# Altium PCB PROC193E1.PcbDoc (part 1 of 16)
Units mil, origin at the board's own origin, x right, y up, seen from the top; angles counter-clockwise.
Board outline 7700 x 2300 mil, 6 copper layers (Top Layer, GND 1, SIG 1, PWR, GND 2, Bottom Layer), stack 60.98 mil thick; 946 components, 667 nets, 9401 pads, 1730 vias.
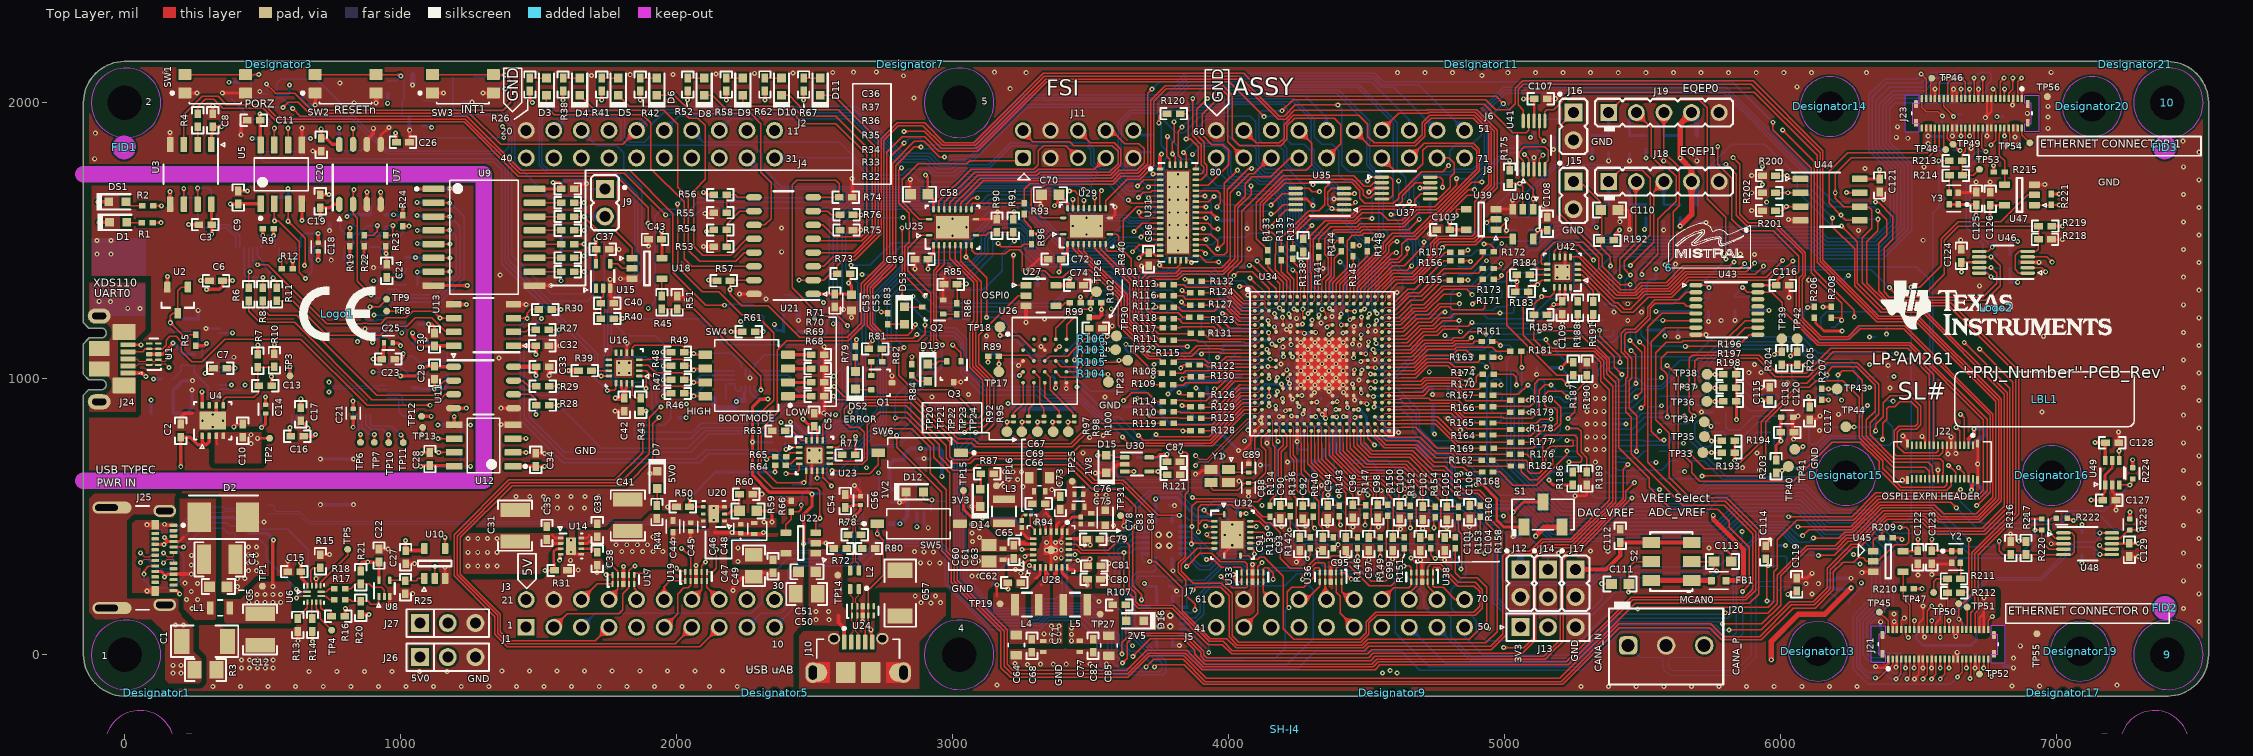
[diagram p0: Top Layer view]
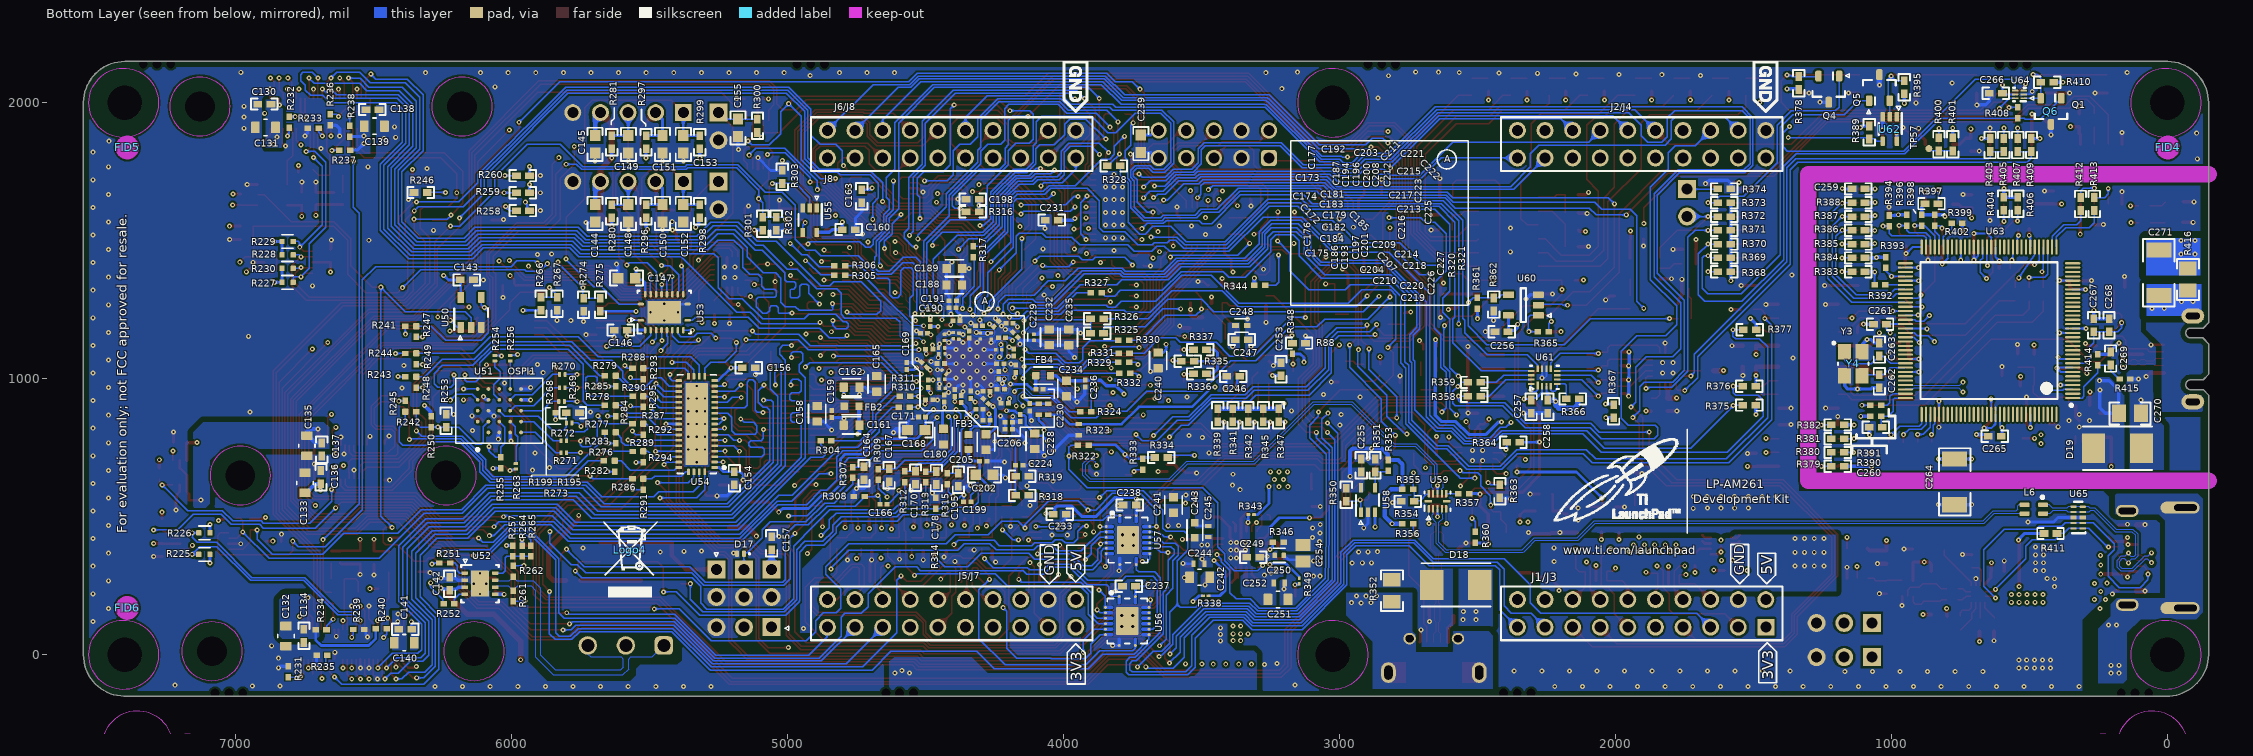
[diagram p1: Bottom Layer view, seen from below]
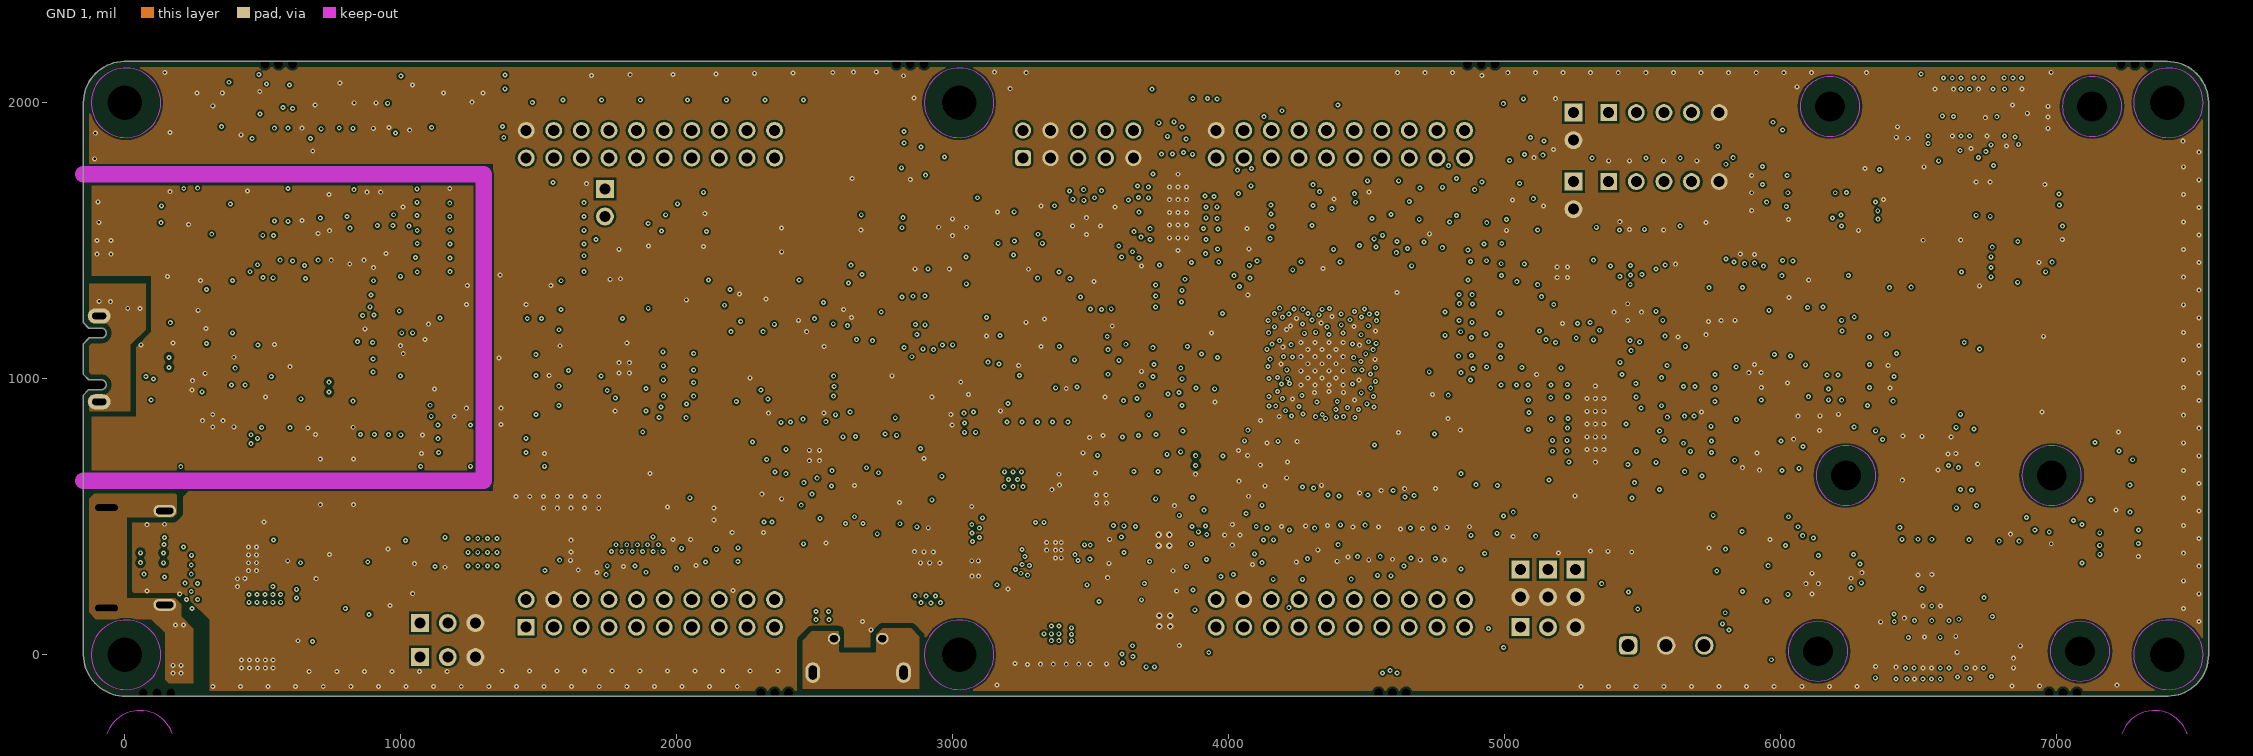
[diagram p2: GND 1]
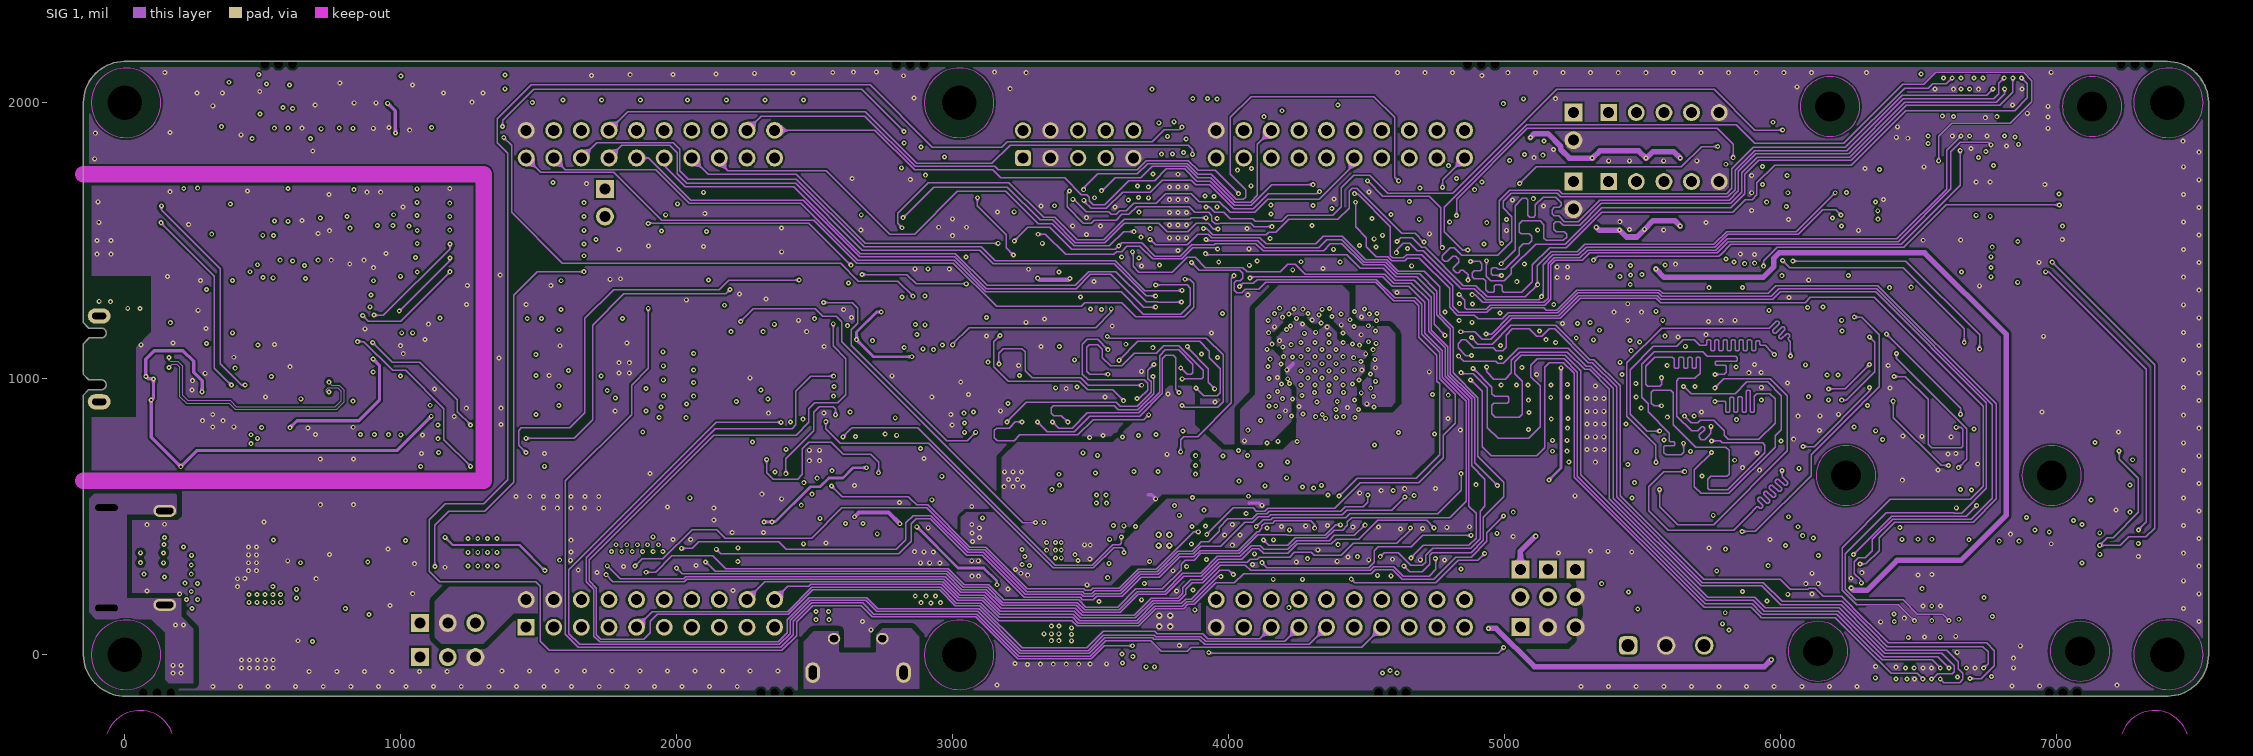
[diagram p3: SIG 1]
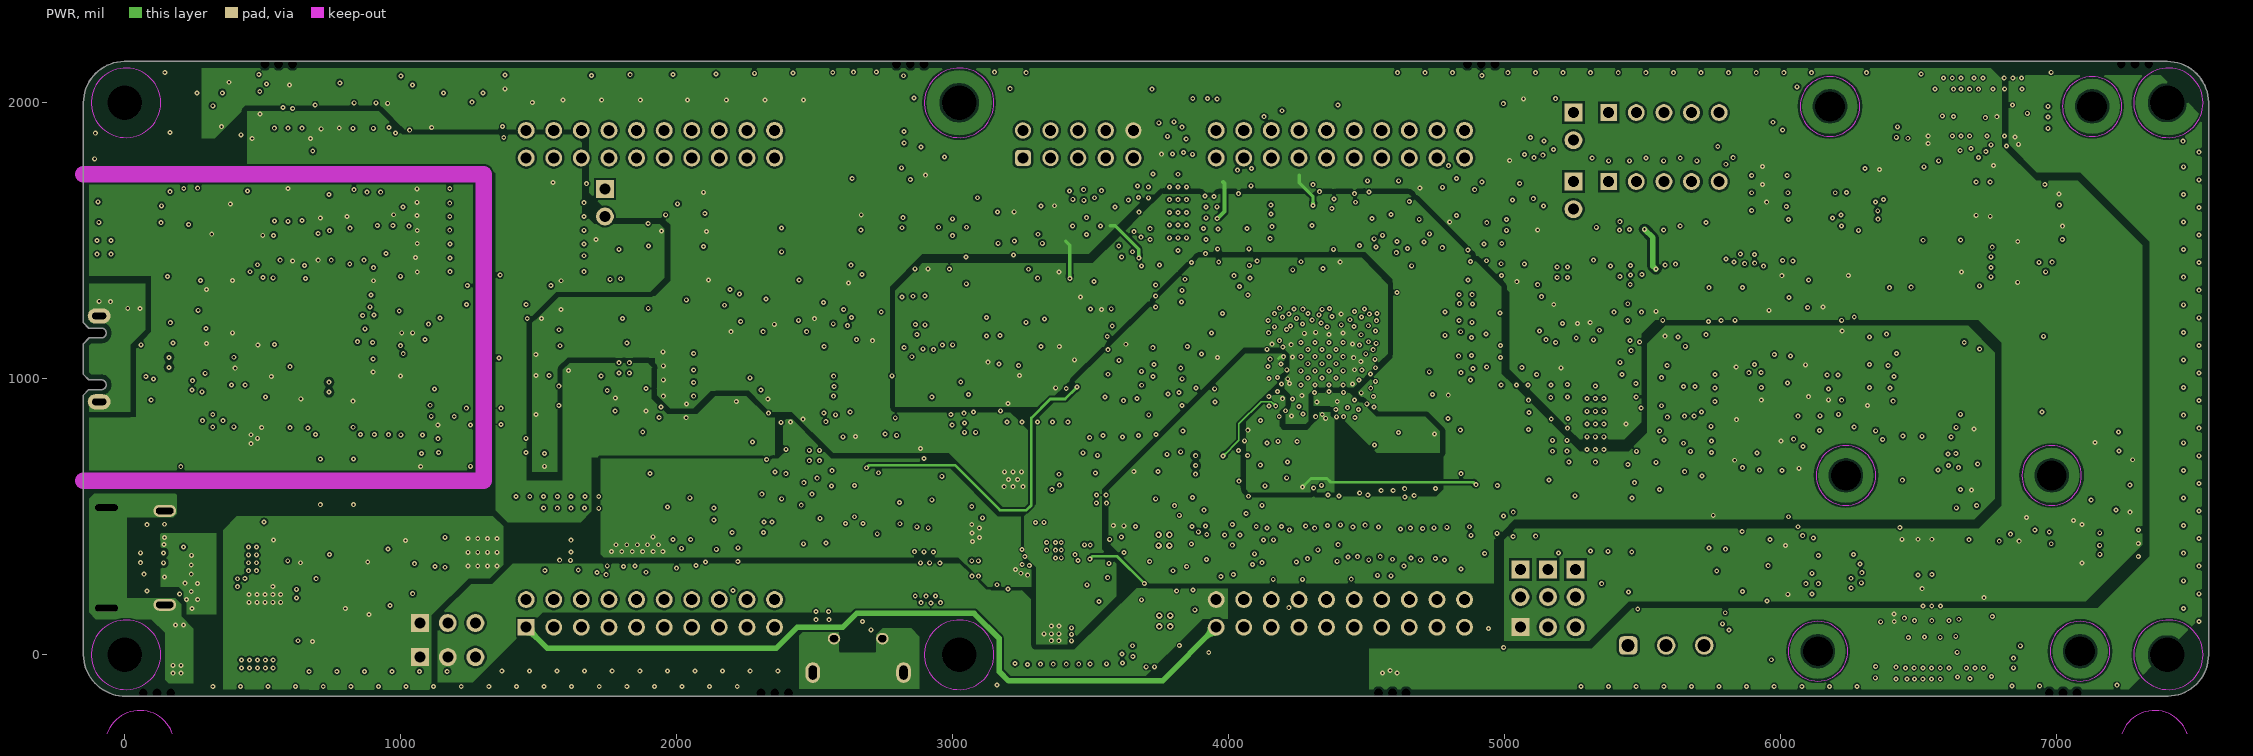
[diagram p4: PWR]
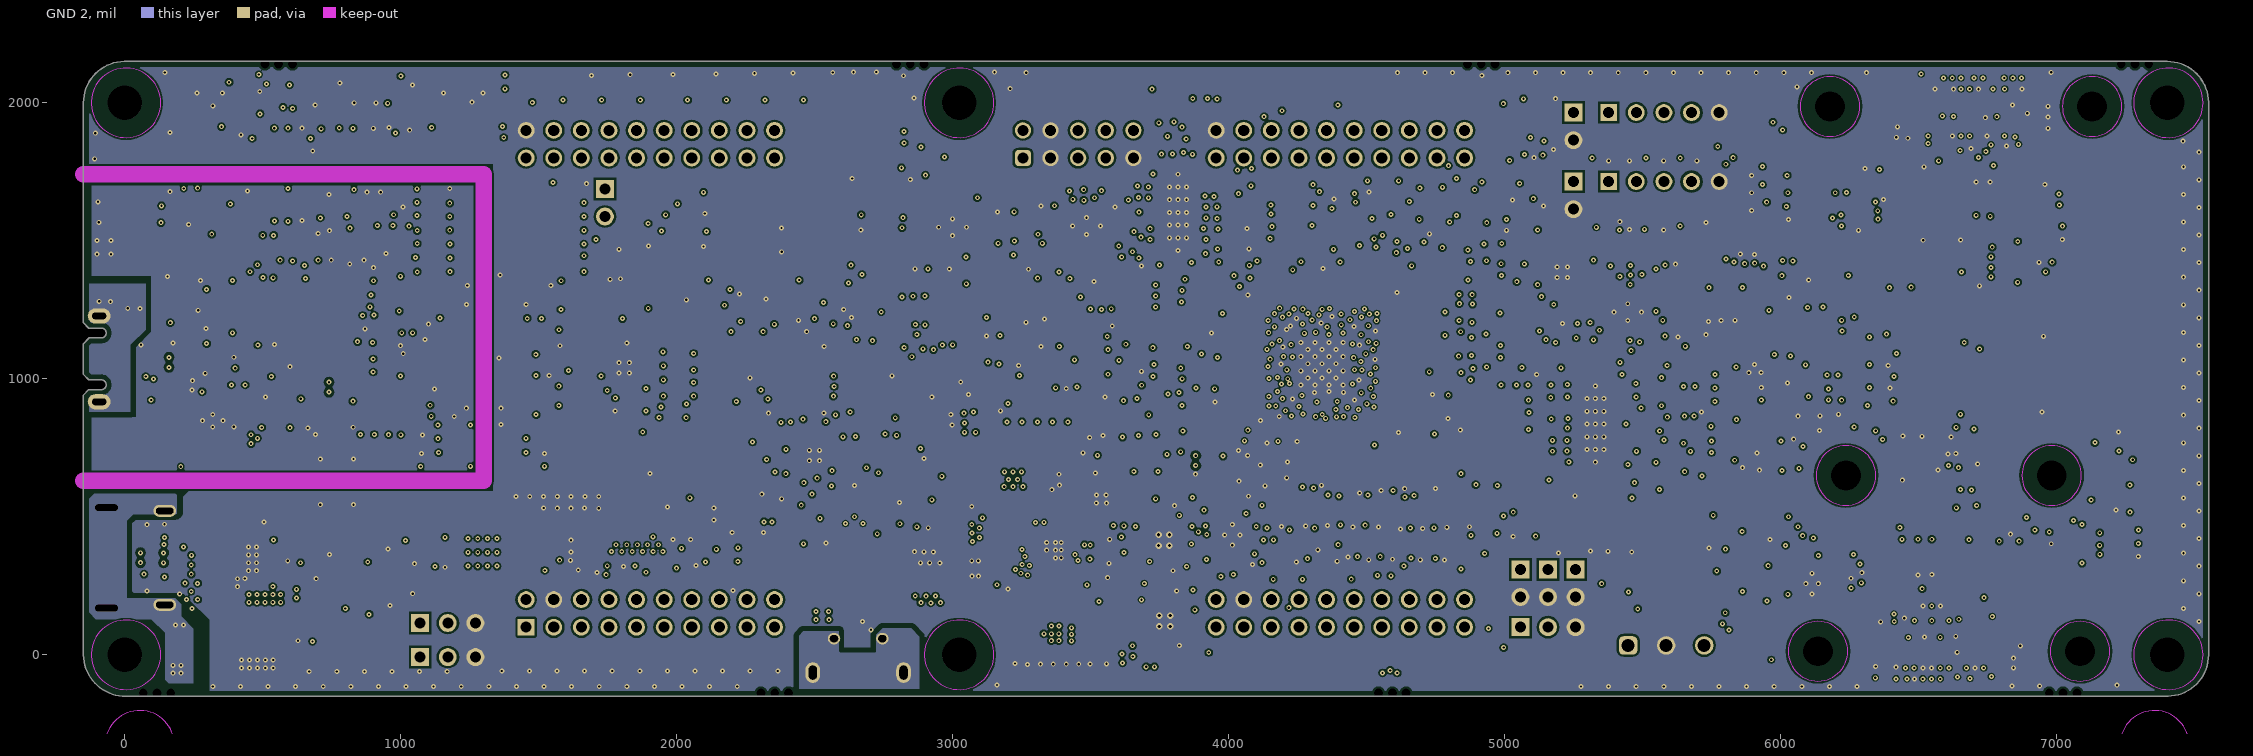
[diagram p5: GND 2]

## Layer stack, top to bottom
Top Solder: solder mask 1, ELECTRA EMP 110/5410- RED, Dk 4
Top Layer: signal copper 1.85
Dielectric 1: prepreg 3.55, Iteq IT180A Prepreg 2113 RC58, Dk 4.13
GND 1: signal copper 1.26
Dielectric 3: core 4, Iteq IT180A 4 mil core 1/1, Dk 4.4
SIG 1: signal copper 1.26
Dielectric 5: core 1.859, Iteq IT180A Prepreg 106 RC71.5, Dk 3.79
Dielectric 7: core 2.711, Iteq IT180A Prepreg 1080 RC65, Dk 3.86
Dielectric1: core 28, Iteq IT180A 28 mil core H/H, Dk 4.53
Dielectric 8: core 2.711, Iteq IT180A Prepreg 1080 RC65, Dk 3.86
Dielectric 6: core 1.859, Iteq IT180A Prepreg 106 RC71.5, Dk 3.79
PWR: signal copper 1.26
Dielectric 4: core 4, Iteq IT180A 4 mil core 1/1, Dk 4.4
GND 2: signal copper 1.26
Dielectric 2: prepreg 3.55, Iteq IT180A Prepreg 2113 RC58, Dk 4.13
Bottom Layer: signal copper 1.85
Bottom Solder: solder mask 1, ELECTRA EMP 110/5410- RED, Dk 4

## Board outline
-150,0 -150,941.28 -130.32,960.97 -84.25,960.97 ccw(c-84.25,977.87) -67.34,977.87 ccw(c-85.87,977.87) -85.87,996.4 -130.32,996.4 -150,1016.08 -150,1127.3 -130.32,1146.99 -130.32,1147.97 -85.04,1147.97 ccw(c-85.04,1165.67) -67.34,1165.67 -67.34,1166.5 ccw(c-84.25,1166.5) -84.25,1183.41 -130.32,1183.41 -150,1203.09 -150,1278.88 -150,1999.99 cw(c0,2000) -2.06,2149.99 0,2150 7399.99,2150 cw(c7400,2000) 7549.99,2002.06 7550,2000 7550,0.01 cw(c7400,0) 7402.06,-149.99 7400,-149.99 0,-150 4.17,-150 cw(c2.09,2.09)

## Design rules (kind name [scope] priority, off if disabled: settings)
AssemblyTestPointUsage [All] p1: valid=2
BoardOutlineClearance BoardOutlineClearance_MountingHoles [OnCopper and InComponentClass('Mounting Holes')] p1: gap=39.37 ignorepadtopadclearanceinfootprint=FALSE
BoardOutlineClearance "Outline Exception" [HasFootprint('Molex_1051640001') or HasFootprint('BRAKE_WAY_HOLES1X3') or HasFootprint('MHNP_M3_PANHEAD_PHILLIPS') or HasFootprint('Fiducial10-20')] p2: gap=0 ignorepadtopadclearanceinfootprint=FALSE
BoardOutlineClearance BoardOutlineClearance_Poly [OnCopper and IsPoly] p3: gap=25 ignorepadtopadclearanceinfootprint=FALSE except(20: Poly-OutlineEdge)
BoardOutlineClearance [OnCopper and Not InComponentClass('Logo') and not InComponentClass('FiducialMark') and not InRegion(1000,500,4000,800) and not InPoly] p4: gap=40 ignorepadtopadclearanceinfootprint=FALSE except(15: SMDPad-OutlineEdge THPad-OutlineEdge; 20: Poly-OutlineEdge; 25: Arc-OutlineEdge Track-OutlineEdge Via-OutlineEdge Fill-OutlineEdge Text-OutlineEdge)
Clearance RGMII_2W_INT [InNetClass('RGMII') and (OnLayer('SIG 1')) vs not InNetClass('RGMII')] p1: gap=7.87 ignorepadtopadclearanceinfootprint=TRUE except(6: SMDPad-SMDPad Via-Fill Via-Poly Via-Region; 7: Via-Via; 7.4: Arc-SMDPad Track-SMDPad; 7.5: SMDPad-Via; 9.5: Arc-Arc Arc-Track Track-Track; 10: Poly-Region; 20: Region-Region; 25: Fill-Fill Fill-Poly Fill-Region Poly-Poly)
Clearance RGMII_INT [InNetClass('RGMII') vs OnLayer('SIG 1')] p2: gap=7.87 ignorepadtopadclearanceinfootprint=TRUE except(6: SMDPad-SMDPad Via-Fill Via-Poly Via-Region; 7: Via-Via; 7.12: Arc-Arc Arc-Track Track-Track; 7.4: Arc-SMDPad Track-SMDPad; 7.5: SMDPad-Via; 10: Poly-Region; 20: Region-Region; 25: Fill-Fill Fill-Poly Fill-Region Poly-Poly)
Clearance RGMII_2W_EXT [InNetClass('RGMII') and OnBottomLayer vs not InNetClass('RGMII')] p3: gap=7.87 ignorepadtopadclearanceinfootprint=TRUE except(6: SMDPad-SMDPad Via-Fill Via-Poly Via-Region; 7: Via-Via; 7.4: Arc-SMDPad Track-SMDPad; 7.5: SMDPad-Via; 10: Poly-Region; 10.6: Arc-Arc Arc-Track Track-Track; 20: Region-Region; 25: Fill-Fill Fill-Poly Fill-Region Poly-Poly)
Clearance RGMII_EXT [InNetClass('RGMII') vs OnLayer('Bottom Layer')] p4: gap=7.87 ignorepadtopadclearanceinfootprint=TRUE except(6: SMDPad-SMDPad Via-Fill Via-Poly Via-Region; 7: Via-Via; 7.12: Arc-Arc Arc-Track Track-Track; 7.4: Arc-SMDPad Track-SMDPad; 7.5: SMDPad-Via; 10: Poly-Region; 20: Region-Region; 25: Fill-Fill Fill-Poly Fill-Region Poly-Poly)
Clearance SOC_POLY_4MIL [WithinRoom('SOC_POLY')] p5: gap=4 ignorepadtopadclearanceinfootprint=TRUE except(3.94: Track-SMDPad; 15: Poly-Poly)
Clearance "Ethernet Conn" [(WithinRoom('Ethernet Conn1') or WithinRoom('Ethernet Conn2')or WithinRoom('12-Pin UQFN') or WithinRoom('Dual Schmitt-Trigger Buffer')or WithinRoom('PMIC') or WithinRoom('Mltplxr/Demltplxr1') or WithinRoom('Mltplxr/Demltplxr2'))] p6: gap=4 ignorepadtopadclearanceinfootprint=TRUE except(8: Region-Region; 12: Poly-Poly)
Clearance 90E_CLR_same [InDifferentialPairClass('90E')] p7: gap=7.87 ignorepadtopadclearanceinfootprint=TRUE except(5: Arc-Arc Arc-Track Track-Track; 10: Via-Fill Via-Poly Via-Region Poly-Region; 12: Via-Via; 20: Region-Region; 25: Fill-Fill Fill-Poly Fill-Region Poly-Poly)
Clearance 90E_CLR [InDifferentialPairClass('90E')] p8: gap=7.87 ignorepadtopadclearanceinfootprint=TRUE except(6: Via-Fill Via-Poly Via-Region; 10: Arc-Arc Arc-Track Track-Track Poly-Region; 12: Via-Via; 20: Region-Region; 25: Fill-Fill Fill-Poly Fill-Region Poly-Poly)
Clearance ADC_EXT [(OnLayer('Top Layer') or OnLayer('Bottom Layer')) vs InNetClass('ADC0')] p9: gap=7.87 ignorepadtopadclearanceinfootprint=TRUE except(5.3: Arc-Arc Arc-Track Track-Track; 6: Via-Fill Via-Poly Via-Region; 10: Poly-Region; 12: Via-Via; 20: Region-Region; 25: Fill-Fill Fill-Poly Fill-Region Poly-Poly)
Clearance ADC_SIG1 [OnLayer('SIG 1') vs InNetClass('ADC0')] p10: gap=7.87 ignorepadtopadclearanceinfootprint=TRUE except(4.75: Arc-Arc Arc-Track Track-Track; 6: Via-Fill Via-Poly Via-Region; 10: Poly-Region; 12: Via-Via; 20: Region-Region; 25: Fill-Fill Fill-Poly Fill-Region Poly-Poly)
Clearance 120E_CLR_same [InDifferentialPairClass('120E')] p11: gap=7.87 ignorepadtopadclearanceinfootprint=TRUE except(6.8: Arc-Arc Arc-Track Track-Track; 10: Via-Fill Via-Poly Via-Region Poly-Region; 12: Via-Via; 20: Region-Region; 25: Fill-Fill Fill-Poly Fill-Region Poly-Poly)
Clearance 120E_CLR [InDifferentialPairClass('120E')] p12: gap=7.87 ignorepadtopadclearanceinfootprint=TRUE except(6: Via-Fill Via-Poly Via-Region; 10: Poly-Region; 12: Via-Via; 15: Arc-Arc Arc-Track Track-Track; 20: Region-Region; 25: Fill-Fill Fill-Poly Fill-Region Poly-Poly)
Clearance DIff_spacing [All vs InDifferentialPair('XDSET_1_D')] p13: gap=7.87 ignorepadtopadclearanceinfootprint=TRUE except(5: Arc-Arc Arc-Track Track-Track; 6: Via-Fill Via-Poly Via-Region; 10: Poly-Region; 12: Via-Via; 20: Region-Region; 25: Fill-Fill Fill-Poly Fill-Region Poly-Poly)
Clearance PMIC_Clearance [InNetClass('PMIC') vs InPolygon] p14: gap=10 ignorepadtopadclearanceinfootprint=TRUE except(4: Via-Fill Via-Poly Via-Region; 12: Fill-Fill Fill-Poly Fill-Region Poly-Poly Poly-Region Region-Region)
Clearance Clearance_FIDUCIAL [HasFootprint('Fiducial10-20')] p15: gap=7.87 ignorepadtopadclearanceinfootprint=TRUE except(0: Arc-SMDPad; 5: Arc-Arc Arc-Track Track-Track; 6: Via-Fill Via-Poly Via-Region; 7: Track-Via; 10: Poly-Region; 12: Via-Via; 20: Poly-Poly Region-Region; 25: Fill-Fill Fill-Poly Fill-Region)
Clearance "Clearance_J4 CONNECTOR" [HasFootprint('FP-DF40GB-48DP-0.4V(58)_HDR48-MFG')] p16: gap=7.87 ignorepadtopadclearanceinfootprint=TRUE except(0: SMDPad-Region; 5: Arc-Arc Arc-Track Track-Track; 6: Via-Fill Via-Poly Via-Region; 7: Track-Via; 10: Poly-Region; 12: Via-Via; 20: Poly-Poly Region-Region; 25: Fill-Fill Fill-Poly Fill-Region)
Clearance [All] p17: gap=7.87 ignorepadtopadclearanceinfootprint=TRUE except(5: Arc-Arc Arc-Track Track-Track; 6: Via-Fill Via-Poly Via-Region; 7: Track-Via; 10: Poly-Region; 12: Via-Via; 20: Poly-Poly Region-Region; 25: Fill-Fill Fill-Poly Fill-Region)
Clearance Clearance_Keepouts [IsKeepOut] p18: gap=1 ignorepadtopadclearanceinfootprint=FALSE
ComponentClearance ComponentClearance_EXCEPTION [HasFootprint('0402_070*')or HasFootprint('0402*')] p1: gap=8 collisioncheckmode=3 verticalgap=8 showdistances=FALSE
ComponentClearance ComponentClearance_MountingHoles_FiducialMarks [InComponentClass('Mounting Holes') vs InComponentClass('FiducialMark')] p2: gap=50 collisioncheckmode=3 verticalgap=10 showdistances=FALSE
ComponentClearance ComponentClearance_Shunt [InComponentClass('Header') vs InComponentClass('Shunt')] p3: gap=0 collisioncheckmode=3 verticalgap=0 showdistances=FALSE
ComponentClearance ComponentClearance_Logo [InComponentClass('Logo')] p4: gap=30 collisioncheckmode=3 verticalgap=10 showdistances=FALSE
ComponentClearance ComponentClearance_ScrewToNut [(HasFootprint('NY PMS 440 0025 PH')) vs (HasFootprint('Keystone_1902C'))] p5: gap=5 collisioncheckmode=3 verticalgap=10 showdistances=FALSE
ComponentClearance ComponentClearance_MountingHoles [InComponentClass('Mounting Holes')] p6: gap=100 collisioncheckmode=3 verticalgap=100000 showdistances=FALSE
ComponentClearance ComponentClearance_SmallPassives [HasFootprint('0201*') or HasFootprint('0508') or HasFootprint('0603*') or HasFootprint('0612') or HasFootprint('0805*') or HasFootprint('0815*') or HasFootprint('0830*') or HasFootprint('1206*') or HasFootprint('1210*') or HasFootprint('1808*') or HasFootprint('1812*') or HasFootprint('1825*') or HasFootprint('2010*') or HasFootprint('2220*') or HasFootprint('2225*') or HasFootprint('2512*') or HasFootprint('2728*') or HasFootprint('3518*') vs HasFootprint('0201*') or HasFootprint('0402*') or HasFootprint('0508') or HasFootprint('0603*') or HasFootprint('0612') or HasFootprint('0805*') or HasFootprint('0815*') or HasFootprint('0830*') or HasFootprint('1206*') or HasFootprint('1210*') or HasFootprint('1808*') or HasFootprint('1812*') or HasFootprint('1825*') or HasFootprint('2010*') or HasFootprint('2220*') or HasFootprint('2225*') or HasFootprint('2512*') or HasFootprint('2728*') or HasFootprint('3518*')] p7: gap=10 collisioncheckmode=3 verticalgap=10 showdistances=FALSE
ComponentClearance ComponentClearance_THtoSMT [IsThruComponent vs IsSMTComponent] p8: gap=30 collisioncheckmode=3 verticalgap=30 showdistances=FALSE
ComponentClearance ComponentClearance_THtoTH [IsThruComponent vs IsThruComponent] p9: gap=20 collisioncheckmode=3 verticalgap=30 showdistances=FALSE
ComponentClearance [All] p10: gap=15 collisioncheckmode=3 verticalgap=15 showdistances=TRUE
DiffPairsRouting 90E [InDifferentialPairClass('90E')] p1: maxlimit=10 minlimit=5 mostfreqgap=6 toplayer_prefgap=5 toplayer_minwidth=4.2 toplayer_maxwidth=15 toplayer_prefwidth=4.2 midlayer1_mingap=6 midlayer1_maxgap=6 midlayer1_minwidth=4 midlayer1_maxwidth=4 midlayer1_prefwidth=4 midlayer2_mingap=6 midlayer2_maxgap=6 midlayer2_minwidth=4 midlayer2_maxwidth=4 midlayer2_prefwidth=4 midlayer3_mingap=10 midlayer3_prefgap=10 midlayer3_minwidth=15 midlayer3_maxwidth=15 midlayer3_prefwidth=15 midlayer4_mingap=10 midlayer4_prefgap=10 midlayer4_minwidth=15 midlayer4_maxwidth=15 midlayer4_prefwidth=15 bottomlayer_prefgap=5 bottomlayer_minwidth=4.2 bottomlayer_maxwidth=15 bottomlayer_prefwidth=4.2 maxuncoupledlength=500
DiffPairsRouting 120E [InDifferentialPair('CANA')] p2: maxlimit=15 minlimit=10 mostfreqgap=10 toplayer_mingap=15 toplayer_prefgap=15 toplayer_minwidth=3.8 toplayer_maxwidth=15 toplayer_prefwidth=3.8 midlayer1_maxgap=10 midlayer1_minwidth=15 midlayer1_maxwidth=15 midlayer1_prefwidth=15 midlayer2_maxgap=10 midlayer2_minwidth=15 midlayer2_maxwidth=15 midlayer2_prefwidth=15 midlayer3_maxgap=10 midlayer3_minwidth=15 midlayer3_maxwidth=15 midlayer3_prefwidth=15 midlayer4_maxgap=10 midlayer4_minwidth=15 midlayer4_maxwidth=15 midlayer4_prefwidth=15 bottomlayer_mingap=15 bottomlayer_prefgap=15 bottomlayer_minwidth=3.8 bottomlayer_maxwidth=15 bottomlayer_prefwidth=3.8 maxuncoupledlength=500
DiffPairsRouting 100E_DIFF [InDifferentialPairClass('100E')] p3: maxlimit=100 minlimit=7.7 mostfreqgap=8.1 toplayer_maxgap=7.7 toplayer_prefgap=7.7 toplayer_minwidth=4 toplayer_maxwidth=4 toplayer_prefwidth=4 midlayer1_mingap=8.1 midlayer1_maxgap=8.1 midlayer1_minwidth=3.5 midlayer1_maxwidth=3.5 midlayer1_prefwidth=3.5 midlayer2_mingap=8.1 midlayer2_maxgap=8.1 midlayer2_minwidth=3.5 midlayer2_maxwidth=3.5 midlayer2_prefwidth=3.5 midlayer3_mingap=10 midlayer3_prefgap=10 midlayer3_minwidth=15 midlayer3_maxwidth=15 midlayer3_prefwidth=15 midlayer4_mingap=10 midlayer4_prefgap=10 midlayer4_minwidth=15 midlayer4_maxwidth=15 midlayer4_prefwidth=15 bottomlayer_maxgap=7.7 bottomlayer_prefgap=7.7 bottomlayer_minwidth=4 bottomlayer_maxwidth=4 bottomlayer_prefwidth=4 maxuncoupledlength=1000
FabricationTestPointUsage TestPointUsage [All] p1: valid=2 allowmultiple=FALSE
FabricationTestpoint Testpoint [All] p1: side=3 testpointundercomponent=TRUE minsize=40 maxsize=100 preferedsize=60 minholesize=0 maxholesize=40 preferedholesize=32 testpointgrid=1 allowsidetop=TRUE allowsidebottom=TRUE usegrid=TRUE gridtolerance=0.01
FanoutControl Fanout_LCC [IsLCC] p1: bgadir=Out bgaviamode=Centered fanoutstyle=Auto fanoutdirection=Alternating viagrid=1 // Fanout_LCC (Default Rule)
FanoutControl Fanout_BGA [IsBGA] p2: bgadir=Out bgaviamode=Centered fanoutstyle=Auto fanoutdirection=Alternating viagrid=1 // Fanout_BGA (Default Rule)
FanoutControl Fanout_Default [All] p4: bgadir=Out bgaviamode=Centered fanoutstyle=Auto fanoutdirection=Alternating viagrid=1 // Fanout_Default (Default Rule)
FanoutControl Fanout_Small [(CompPinCount < 5)] p5: bgadir=Out bgaviamode=Centered fanoutstyle=Auto fanoutdirection=OutThenIn viagrid=1 // Fanout_Small (Default Rule)
HoleSize [All] p1: absolutevalues=TRUE maxlimit=251 minlimit=7.87 maxpercent=80.000 minpercent=20.000
MatchedLengths XDSET [(InDifferentialPair('XDSET_1_D') or InDifferentialPair('AM261_USB2.0') or InDifferentialPair('CANA') or InDifferentialPair('USBMICROAB') or InDifferentialPair('USBMICROAB_C') or InDifferentialPair('USBTYPEC') or InDifferentialPair('USBTYPEC_C'))] p1: tolerance=1 checknetsindiffpair=TRUE checkdiffpairvsdiffpair=FALSE checkxsignals=FALSE checkothers=FALSE
MatchedLengths USB_TYPEC [InNetClass('USB_TYPEC')] p2: tolerance=10 checknetsindiffpair=TRUE checkdiffpairvsdiffpair=FALSE checkxsignals=FALSE checkothers=FALSE
MatchedLengths OPSI1_U34_U54 [InxSignalClass('OSPI1_U34_U54')] p3: tolerance=50 checknetsindiffpair=FALSE checkdiffpairvsdiffpair=TRUE checkxsignals=TRUE checkothers=TRUE targetsourcename=NetR218_2-AM261_OSPI1_CLK/FSITX0_CLK_PP1
MatchedLengths OSPI1_U54_J22 [InxSignalClass('OSPI1_U54_J22')] p4: tolerance=50 checknetsindiffpair=FALSE checkdiffpairvsdiffpair=TRUE checkxsignals=TRUE checkothers=TRUE targetsourcename=M_OSPI1_CLK-EX_OSPI1_CLK_PP2
MatchedLengths OSPI1_U54_51 [InxSignalClass('OSPI1_U54_U51')] p5: tolerance=50 checknetsindiffpair=FALSE checkdiffpairvsdiffpair=TRUE checkxsignals=TRUE checkothers=TRUE targetsourcename=M_OSPI1_CLK-OSPI1_CLK_PP1
MatchedLengths OSPI0_U34_U26 [InxSignalClass('OSPI0_U34_U26')] p6: tolerance=50 checknetsindiffpair=FALSE checkdiffpairvsdiffpair=TRUE checkxsignals=TRUE checkothers=TRUE targetsourcename=AM261_OSPI0_CLK
MatchedLengths RGMII1_TX [InxSignalClass('RGMII1_TX')] p7: tolerance=15 checknetsindiffpair=FALSE checkdiffpairvsdiffpair=TRUE checkxsignals=TRUE checkothers=TRUE targetsourcename=AM261_RGMII1_TD0_R-AM261_RGMII1_TD0_PP1
MatchedLengths RGMII1_RX [InxSignalClass('RGMII1_RX')] p8: tolerance=15 checknetsindiffpair=FALSE checkdiffpairvsdiffpair=TRUE checkxsignals=TRUE checkothers=TRUE targetsourcename=AM261_RGMII1_RD0_PP1
MatchedLengths RGMII2_TX [InxSignalClass('RGMII2_TX')] p9: tolerance=15 checknetsindiffpair=FALSE checkdiffpairvsdiffpair=TRUE checkxsignals=TRUE checkothers=TRUE targetsourcename=AM261_RGMII2_TD3-AM261_RGMII2_TD3_R_PP1
MatchedLengths RGMII2_RX [InxSignalClass('RGMII2_RX')] p10: tolerance=15 checknetsindiffpair=FALSE checkdiffpairvsdiffpair=TRUE checkxsignals=TRUE checkothers=TRUE targetsourcename=AM261_RGMII2_RD2_PP1
MinimumAnnularRing MinimumAnnularRing_ThermalPadVias [IsVia and InAnyComponent] p1: minimumring=5.91
MinimumAnnularRing [All] p2: minimumring=5
MinimumSolderMaskSliver MinimumSolderMaskSliver_Logo [InComponentClass('Logo') vs InComponentClass('Logo')] p1: minsoldermaskwidth=0.7
PlaneConnect [All] p1: planeconnectstyle=Direct reliefexpansion=10 reliefentries=4 reliefconductorwidth=10 reliefairgap=10
PolygonConnect PolygonConnect_3 [All vs IsNamedPolygon('SIG 2-vusb_3v3')] p1: connectstyle=Direct reliefconductorwidth=10 reliefentries=4 polygonreliefangle="90 Angle" airgapwidth=10
PolygonConnect PolygonConnect_2 [All vs IsNamedPolygon('Top Layer-VBUS_TYPEC_5V0')] p2: connectstyle=Direct reliefconductorwidth=10 reliefentries=4 polygonreliefangle="90 Angle" airgapwidth=10
PolygonConnect PolygonConnect_1 [All vs IsNamedPolygon('Top Layer-VBUS_TYPEC_5V0')] p3: connectstyle=Direct reliefconductorwidth=10 reliefentries=4 polygonreliefangle="90 Angle" airgapwidth=10
PolygonConnect [All] p4: connectstyle=Direct reliefconductorwidth=10 reliefentries=4 polygonreliefangle="90 Angle" airgapwidth=10
RoomDefinition Mltplxr/Demltplxr2 [InComponentClass('Room Definition8') vs False] p1: confinementstyle=ConfineIn formatcopy=TRUE lockcomponents=FALSE outline 3668.27,12.92 3668.27,264.38 3867.56,264.38 3867.56,12.92
RoomDefinition Mltplxr/Demltplxr1 [InComponentClass('Room Definition7') vs False] p2: confinementstyle=ConfineIn formatcopy=TRUE lockcomponents=FALSE outline 3665.4,306.14 3665.4,557.59 3864.69,557.59 3864.69,306.14
RoomDefinition PMIC [InComponentClass('Room Definition6') vs False] p3: confinementstyle=ConfineIn formatcopy=TRUE lockcomponents=FALSE outline 3240.34,274.86 3240.34,510.97 3459.53,510.97 3459.53,274.86
RoomDefinition "Dual Schmitt-Trigger Buffer" [InComponentClass('Room Definition5') vs False] p4: confinementstyle=ConfineIn formatcopy=TRUE lockcomponents=FALSE outline 491.1,1986.65 491.1,2073.74 579.76,2073.74 579.76,1986.65
RoomDefinition "12-Pin UQFN" [InComponentClass('Room Definition4') vs False] p5: confinementstyle=ConfineIn formatcopy=TRUE lockcomponents=FALSE outline 2577.63,461.21 2577.63,637.57 2710,637.57 2710,461.21
RoomDefinition "Ethernet Conn2" [InComponentClass('Room Definition3') vs False] p6: confinementstyle=ConfineIn formatcopy=TRUE lockcomponents=FALSE outline 6303.2,-125 6303.2,205.39 6819.03,205.39 6819.03,-125
RoomDefinition "Ethernet Conn1" [InComponentClass('Room Definition2') vs False] p7: confinementstyle=ConfineIn formatcopy=TRUE lockcomponents=FALSE outline 6434.39,1826 6434.39,2126 6950.22,2126 6950.22,1826
RoomDefinition SOC_POLY [False] p8: confinementstyle=ConfineIn formatcopy=TRUE lockcomponents=FALSE outline 4043.66,767.84 4043.66,1348.43 4624.25,1348.43 4624.25,767.84
RoutingLayers [All] p1: top layer_v5=TRUE mid layer 1_v5=TRUE mid layer 2_v5=TRUE mid layer 3_v5=FALSE mid layer 4_v5=TRUE bottom layer_v5=TRUE
RoutingVias ThermalPadVias [IsVia and InAnyComponent] p1: holewidth=7.87 width=19.68 viastyle="Through Hole" minholewidth=7.87 minwidth=19.68 maxholewidth=12.99 maxwidth=23.62
RoutingVias [All] p2: holewidth=8 width=18 viastyle="Through Hole" minholewidth=8 minwidth=18 maxholewidth=8 maxwidth=18
SilkToBoardRegionClearance [Not ((IsComment or IsDesignator) And (Hide <> 'False')) and not InRegion(1000,500,4000,800)] p1:
SilkToSilkClearance SilkToSilkClearance_Pb-FreeLogo [(HasFootprint('Pb-Free_Overlay_Medium') OR HasFootprint('Pb-Free_Overlay_Small')) vs (HasFootprint('Pb-Free_Overlay_Medium') OR HasFootprint('Pb-Free_Overlay_Small'))] p1: silktosilkclearance=0
SilkToSilkClearance [All] p2: silktosilkclearance=2
SilkToSolderMaskClearance SilkToComponentPadClearance [(IsPad or IsFill or IsRegion) and Component] p1: minsilkscreentomaskgap=3.54 clearancetoexposedcopper=TRUE
SilkToSolderMaskClearance "Silk to Solder Mask Opening" [All] p2: minsilkscreentomaskgap=1 clearancetoexposedcopper=FALSE
SolderMaskExpansion [All] p1: expansion=1.97 istentingtop=FALSE
UnRoutedNet [All] p1: checkbadconnections=TRUE
Width BGA-trace [All] p1: maxlimit=100 minlimit=3.94 preferedwidth=4.75 toplayer_prefwidth=3.94 midlayer1_minwidth=4.75 midlayer2_minwidth=4.75 midlayer3_minwidth=5.3 midlayer3_prefwidth=5.3 midlayer4_minwidth=5.3 midlayer4_prefwidth=5.3 bottomlayer_prefwidth=3.94 minimp=50.000000 maximp=50.000000 favimp=50.000000 checkconnectedcopper=TRUE
Width PWR [InNetClass('POWER')] p2: maxlimit=30 minlimit=6 preferedwidth=12 midlayer1_minwidth=8 midlayer2_minwidth=8 midlayer3_minwidth=8 midlayer4_minwidth=8 bottomlayer_minwidth=7 minimp=50.000000 maximp=50.000000 favimp=50.000000
Width [All] p3: maxlimit=100 minlimit=4.75 preferedwidth=5.3 toplayer_minwidth=5.3 midlayer1_prefwidth=4.75 midlayer2_prefwidth=4.75 midlayer3_minwidth=5.3 midlayer4_minwidth=5.3 bottomlayer_minwidth=5.3 minimp=50.000000 maximp=50.000000 favimp=50.000000 checkconnectedcopper=TRUE
13 further rules are at their usual default settings.

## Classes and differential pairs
net class USB_TYPEC: USBTYPEC_C_DM USBTYPEC_C_DP
net class 4MIL_SOC: AM261_ADC0_AIN0_R AM261_ADC0_AIN2_R AM261_ADC0_AIN5_R AM261_ADC1_AIN0_R AM261_ADC1_AIN3_R AM261_ADC1_AIN5_R AM261_ADC1_AIN6_R AM261_ADC2_AIN0_R AM261_ADC2_AIN3_R AM261_ADC2_AIN4_R AM261_CLKOUT1_R AM261_DAC_OUT_R AM261_EPWM2_B_R AM261_EPWM3_B_R AM261_EPWM4_A_R AM261_EPWM5_A_R AM261_EPWM6_A_R AM261_EPWM7_A_R AM261_EPWM7_B_R AM261_GPIO1 AM261_GPIO136 AM261_I2C0_SDA AM261_I2C1_SCL AM261_LIN2_RXD AM261_MCAN0_RX AM261_MCAN1_RX AM261_MCAN1_TX AM261_MII2_COL AM261_OSPI1_DQS/EQEP1_STROBE AM261_PORZ AM261_RGMII1_RD1 AM261_RGMII1_RX_CTL AM261_RGMII1_RXC AM261_RGMII1_TD3_R AM261_RGMII2_RD1 AM261_RGMII2_TD1_R AM261_RGMII2_TD3_R AM261_RGMII2_TXC_R AM261_RMII1_CRS_DV/MII1_CRS AM261_RMII2_RX_ER/MII2_RX_ER AM261_SPI0_CS0 AM261_SPI2_D1 AM261_UART3_TXD_R AM261_USB0_DRVVBUS NetR108_2 NetR109_2 NetR125_2 NetR126_2 NetR128_2 NetR129_2 NetR137_2 NetR138_2 NetR144_2 NetR145_2 NetR166_2 NetR167_2 NetR176_2 NetR177_2 NetR178_2 NetR182_2 NetR331_2 PR1_PRU0_GPIO0 PR1_PRU0_GPIO2 PR1_PRU0_GPIO5 PR1_PRU0_GPIO8 PR1_PRU1_GPIO0 PR1_PRU1_GPIO2 PR1_PRU1_GPIO13
net class FSI_U9-U46: M_FSITX0_CLK M_FSITX0_DATA0 M_FSITX0_DATA1
net class FSI_U9-U41: M_FSIRX0_CLK M_FSIRX0_DATA0/EQEP0_A M_FSIRX0_DATA1/EQEP0_B
net class FSI_U41-U46: FSIRX0_CLK FSIRX0_DATA0 FSIRX0_DATA1
net class FSI_U46-J23: FSIRX0_C FSIRX0_D0 FSIRX0_D1 FSITX0_C FSITX0_D0 FSITX0_D1
net class OSPI: AM261_OSPI0_CLK AM261_OSPI0_CSN0 AM261_OSPI0_D0 AM261_OSPI0_D1 AM261_OSPI0_D2 AM261_OSPI0_D3 AM261_OSPI0_D4 AM261_OSPI0_D5 AM261_OSPI0_D6 AM261_OSPI0_D7 AM261_OSPI0_DQS AM261_OSPI0_DQS_R AM261_OSPI0_ECC_FAIL AM261_OSPI0_RESET_OUT0 AM261_OSPI1_CLK/FSITX0_CLK AM261_OSPI1_CSN0/EQEP1_B AM261_OSPI1_D0/FSITX0_DATA0 AM261_OSPI1_D1/FSITX0_DATA1 AM261_OSPI1_D2/FSIRX0_CLK AM261_OSPI1_D3/FSIRX0_DATA0/EQEP0_A AM261_OSPI1_D4/FSIRX0_DATA1/EQEP0_B AM261_OSPI1_D5/EQEP0_INDEX AM261_OSPI1_D6/EQEP0_STROBE AM261_OSPI1_D7/EQEP1_A AM261_OSPI1_DQS/EQEP1_STROBE AM261_OSPI1_ECC_FAIL/EQEP1_INDEX AM261_OSPI1_RESET_OUT0 EX_OSPI1_CLK EX_OSPI1_CSN0 EX_OSPI1_CSN1 EX_OSPI1_D0 EX_OSPI1_D1 EX_OSPI1_D2 EX_OSPI1_D3 EX_OSPI1_D4 EX_OSPI1_D5 EX_OSPI1_D6 EX_OSPI1_D7 EX_OSPI1_DQS_R EX_OSPI1_ECC_FAIL EX_OSPI1_RSTn M_OSPI1_CLK M_OSPI1_CSN0 M_OSPI1_D0 M_OSPI1_D1 M_OSPI1_D2 M_OSPI1_D3 M_OSPI1_D4 M_OSPI1_D5 M_OSPI1_D6 M_OSPI1_D7 M_OSPI1_DQS M_OSPI1_ECC_FAIL OSPI0_D0 OSPI0_D1 OSPI0_D2 OSPI0_D3 OSPI0_D4 OSPI0_D5 OSPI0_D6 OSPI0_D7 OSPI0_RESET_OUT0 OSPI0_RSTn OSPI1_CLK OSPI1_CSN0 OSPI1_D0 OSPI1_D0_R OSPI1_D1 OSPI1_D1_R OSPI1_D2 OSPI1_D2_R OSPI1_D3 OSPI1_D3_R OSPI1_D4 OSPI1_D4_R OSPI1_D5 OSPI1_D5_R OSPI1_D6 OSPI1_D6_R OSPI1_D7 OSPI1_D7_R OSPI1_DQS OSPI1_DQS_R OSPI1_ECC_FAIL OSPI1_MUX_EN OSPI1_MUX_SEL OSPI1_RESET_OUT0 OSPI1_RSTn OSPI1_RSTn_R
net class 120E: CANA_N CANA_P
component class PROC193E1_19_USB_XDS110: C2 C10 C13 C14 C270 C271 D19 J24 R7 R10 R416 TP2 TP3 TP12 TP13 U1 U4
net class RGMII: AM261_RGMII1_RD0 AM261_RGMII1_RD1 AM261_RGMII1_RD2 AM261_RGMII1_RD3 AM261_RGMII1_RX_CTL AM261_RGMII1_RXC AM261_RGMII1_TD0 AM261_RGMII1_TD1 AM261_RGMII1_TD2 AM261_RGMII1_TD3 AM261_RGMII1_TX_CTL AM261_RGMII1_TXC AM261_RGMII2_RD0 AM261_RGMII2_RD1 AM261_RGMII2_RD2 AM261_RGMII2_RD3 AM261_RGMII2_RX_CTL AM261_RGMII2_RXC AM261_RGMII2_TD0 AM261_RGMII2_TD1 AM261_RGMII2_TD2 AM261_RGMII2_TD3 AM261_RGMII2_TX_CTL AM261_RGMII2_TXC AM261_RMII1_RX_ER/MII1_RX_ER AM261_RMII2_RX_ER/MII2_RX_ER
net class ADC0: AM261_ADC0_AIN0 AM261_ADC0_AIN0_R AM261_ADC0_AIN1 AM261_ADC0_AIN1_R AM261_ADC0_AIN2 AM261_ADC0_AIN2_R AM261_ADC0_AIN3 AM261_ADC0_AIN3_R AM261_ADC0_AIN4 AM261_ADC0_AIN4_R AM261_ADC0_AIN5 AM261_ADC0_AIN5_R AM261_ADC0_AIN6 AM261_ADC0_AIN6_R AM261_ADC1_AIN0 AM261_ADC1_AIN0_R AM261_ADC1_AIN1 AM261_ADC1_AIN1_R AM261_ADC1_AIN2 AM261_ADC1_AIN2_R AM261_ADC1_AIN3 AM261_ADC1_AIN3_R AM261_ADC1_AIN4 AM261_ADC1_AIN4_R AM261_ADC1_AIN5 AM261_ADC1_AIN5_R AM261_ADC1_AIN6 AM261_ADC1_AIN6_R AM261_ADC2_AIN0 AM261_ADC2_AIN0_R AM261_ADC2_AIN2 AM261_ADC2_AIN2_R AM261_ADC2_AIN3 AM261_ADC2_AIN3_R AM261_ADC2_AIN4 AM261_ADC2_AIN4_R AM261_ADC2_AIN5 AM261_ADC2_AIN5_R AM261_ADC2_AIN6 AM261_ADC2_AIN6_R AM261_ADC_CAL0 AM261_ADC_CAL0_R AM261_ADC_VREFHI_G0 AM261_ADC_VREFHI_G1 AM261_ADC_VREFLO_G0 AM261_ADC_VREFLO_G1
net class POWER: VBUS_MICRO_AB_5V0 VBUS_XDS_5V0
net class PMIC: NetL4_1 NetL5_1 VSYS_5V0
differential pair class 120E: CANA
differential pair class 90E: AM261_USB2.0 USBMICROAB USBMICROAB_C USBTYPEC USBTYPEC_C XDSET_1_D
net class 90E: AM261_USB2.0_DM AM261_USB2.0_DP USBMICROAB_C_DM USBMICROAB_C_DP USBMICROAB_DM USBMICROAB_DP USBTYPEC_C_DM USBTYPEC_C_DP USBTYPEC_DM USBTYPEC_DP
component class PROC193E1_17_BPMuxes: C86 C103 C107 C108 C160 C163 C231 C233 C237 C238 R90 R91 R175 R266 R267 R301 R302 R303 U31 U32 U37 U39 U40 U41 U55 U56 U57
component class PROC193E1_10_USB_I2C0_IOEXP: C52 C109 R63 R64 R65 R77 R183 R184 R185 R188 R191 R364 U23 U42
component class PROC193E1_08_OSPI1_Conn: C115 C117 C118 C120 C133 C135 C136 C137 C143 J22 R193 R194 R195 R196 R197 R198 R199 R203 R204 R205 R206 R207 R208 R241 R242 R243 R244 R245 R247 R248 R249 R250 R253 R254 R255 R256 R263 R268 R269 R270 R271 R272 R273 R276 R277 R278 R279 R282 R283 R284 R285 R286 R287 R288 R289 R290 R291 R292 R293 R294 R295 TP33 TP34 TP35 TP36 TP37 TP38 TP39 TP40 TP41 TP42 TP43 TP44 U50 U51
component class PROC193E1_21_XDS110_2: C3 C6 C7 C8 C16 C17 C18 C21 C23 C24 C25 C29 C30 C32 C33 C260 C261 C262 C263 C264 C265 C267 C268 C269 D1 DS1 R1 R2 R4 R5 R6 R8 R9 R11 R12 R19 R22 R23 R24 R27 R28 R29 R390 R391 R392 R393 R394 R396 R398 R399 R402 R412 R413 R414 R415 TP6 TP7 TP9 TP10 TP11 U2 U3 U11 U13 U63 Y4
component class PROC193E1_20_USB_TYPE_MicroAB: C47 C49 C50 C51 C54 C56 C57 D18 J10 L2 R66 R72 R78 R80 R352 R354 R355 R356 R357 R360 SW5 SW6 TP14 TP55 U22 U24 U59
component class PROC193E1_12_Ehernet_Conn_0: C122 C123 C132 C134 C140 C141 J21 R209 R210 R211 R212 R225 R226 R231 R234 R235 R239 R240 TP45 TP47 TP50 TP51 TP52 U45 Y2
component class PROC193E1_03_DerbyPMIC_PWR: C60 C61 C62 C63 C64 C65 C66 C67 C68 C69 C71 C73 C75 C76 C77 C78 C79 C80 C81 C82 C83 C84 C85 C87 C242 C243 C244 C245 C249 C250 C251 C252 C254 C255 D12 D14 D15 D16 L3 L4 L5 R87 R94 R107 R121 R333 R334 R338 R343 R346 R349 R350 R351 R353 TP15 TP16 TP19 TP25 TP27 TP31 U28 U30 U58
component class PROC193E1_02_USB_TYPEC_IN_PWR: C1 C4 C5 C12 C15 C22 C27 C31 C35 C38 C39 C41 D2 J25 L1 L6 R3 R13 R14 R15 R16 R17 R18 R20 R21 R25 R31 R411 TP1 TP4 TP5 TP56 U6 U8 U10 U14 U65
component class PROC193E1_14_Push_Buttons: C26 C266 Q4 Q5 Q6 R378 R389 R395 R408 R410 SW1 SW2 SW3 U62 U64
component class PROC193E1_22_LED: C53 C55 D3 D4 D5 D6 D7 D8 D9 D10 D11 D13 DS2 DS3 Q1 Q2 Q3 R26 R38 R41 R42 R44 R52 R53 R54 R55 R56 R58 R62 R67 R74 R75 R76 R79 R81 R82 R83 R84 R85 R86 R325 U21
component class PROC193E1_13_Ehernet_Conn_1: C125 C126 C130 C131 C138 C139 J23 R213 R214 R215 R221 R227 R229 R232 R233 R236 R237 R238 TP46 TP48 TP49 TP53 TP54 U47 Y3
component class PROC193E1_04_VPP1V7_PWR: C44 C45 C46 C48 R50 R59 R60 U20
component class PROC193E1_18_Breakout_Headers: C58 C59 C110 C114 C116 C119 C142 C144 C145 C146 C147 C148 C149 C150 C151 C152 C153 C155 C239 J11 J15 J16 J18 J19 J20 R93 R96 R192 R251 R252 R257 R261 R262 R264 R265 R274 R275 R280 R281 R296 R297 R298 R299 R300 U25 U43 U52 U53
component class PROC193E1_16_Boosterpack_Headers: C70 C72 C198 J1/J3 J2/J4 J5/J7 J6/J8 J13 J26 J27 R316 R363 U29 U35
component class PROC193E1_15_Test_Automation: C9 C11 C19 C20 C28 C34 C36 C259 J9 R32 R33 R34 R35 R36 R37 R367 R368 R369 R370 R371 R372 R373 R374 R379 R380 R381 R382 R383 R384 R385 R386 R387 R388 R397 R400 R401 R403 R404 R405 R406 R407 R409 TP8 TP57 U5 U7 U9 U12
component class PROC193E1_07_OSPI_eQEP_FSI: C74 C154 C156 C246 C247 C248 C253 R57 R73 R88 R89 R92 R95 R97 R98 R99 R100 R101 R102 R103 R104 R105 R106 R109 R110 R111 R112 R113 R114 R115 R116 R117 R118 R119 R120 R123 R124 R125 R127 R128 R129 R131 R132 R138 R141 R144 R145 R148 R162 R164 R165 R166 R168 R169 R176 R177 R178 R179 R182 R186 R187 R189 R190 R223 R224 R310 R311 R317 R322 R328 R331 R332 R335 R336 R337 R339 R340 R341 R342 R344 R345 R347 R348 R358 R359 TP17 TP18 TP20 TP21 TP22 TP23 TP24 TP26 TP28 TP29 TP30 TP32 U26 U27 U54
component class PROC193E1_11_RGMII_MII: C124 C127 C128 C129 R108 R122 R126 R130 R133 R135 R137 R155 R156 R157 R161 R163 R167 R170 R171 R172 R173 R174 R180 R181 R216 R217 R218 R219 R220 R222 R228 R230 R304 R305 R306 R324 R329 R330 U46 U48 U49
component class PROC193E1_06_Clock_Reset_Boot_JTAG: C37 C40 C42 C43 C88 C89 C121 C256 C257 C258 R30 R39 R40 R43 R45 R46 R47 R48 R49 R51 R61 R68 R69 R70 R71 R200 R201 R202 R246 R258 R259 R260 R326 R327 R361 R362 R365 R366 R375 R376 R377 SW4 U15 U16 U18 U44 U60 U61 Y1
component class PROC193E1_05_SoC_Power: C111 C113 C158 C159 C161 C162 C165 C166 C168 C169 C171 C172 C173 C174 C175 C176 C177 C179 C180 C181 C182 C183 C184 C185 C186 C187 C188 C189 C190 C191 C192 C193 C194 C196 C197 C199 C200 C201 C202 C203 C204 C205 C206 C207 C208 C209 C210 C211 C212 C213 C214 C215 C216 C217 C218 C219 C220 C221 C222 C223 C224 C225 C226 C227 C228 C229 C230 C232 C234 C235 C236 C240 C241 FB2 FB3 FB4 R308 R314 R318 R319 R320 R321 R323 U34
component class PROC193E1_09_ADC_DAC: C90 C91 C92 C93 C94 C95 C96 C97 C98 C99 C100 C101 C102 C104 C105 C106 C112 C157 C164 C167 C170 C178 C195 D17 FB1 J12 J14 J17 R134 R136 R139 R140 R142 R143 R146 R147 R149 R150 R151 R152 R153 R154 R158 R159 R160 R307 R309 R312 R313 R315 S1 S2 U17 U19 U33 U36 U38
component class PROC193E1_23_Systemhardware_notes_labels: FID1 FID2 FID3 FID4 FID5 FID6 LBL1 Logo1 Logo2 Logo3 Logo4 SH-J1 SH-J2 SH-J3 SH-J4 SH-J5 SH-J6 SH-J7 SH-J8 ZZ1 ZZ2 ZZ3 ZZ4
differential pair USBTYPEC_C: +USBTYPEC_C_DP -USBTYPEC_C_DM
differential pair USBTYPEC: +USBTYPEC_DP -USBTYPEC_DM
differential pair AM261_USB2.0: +AM261_USB2.0_DP -AM261_USB2.0_DM
differential pair USBMICROAB_C: +USBMICROAB_C_DP -USBMICROAB_C_DM
differential pair USBMICROAB: +USBMICROAB_DP -USBMICROAB_DM
differential pair XDSET_1_D: +XDSET_1_D_P -XDSET_1_D_N
differential pair CANA: +CANA_P -CANA_N

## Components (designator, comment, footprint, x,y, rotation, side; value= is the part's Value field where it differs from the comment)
1 "Comment" MHNP_M3_PANHEAD_PHILLIPS#1 4.17,0 r0 top locked
2 "Comment" MHNP_M3_PANHEAD_PHILLIPS#1 4.17,2000 r0 top locked
3 "Comment" MHNP_M3_PANHEAD_PHILLIPS#2 54.16,-327.94 r0 top locked
4 "Comment" MHNP_M3_PANHEAD_PHILLIPS#2 3023.18,0 r0 top
5 "Comment" MHNP_M3_PANHEAD_PHILLIPS#2 3023.18,2000 r0 top locked
6 "Comment" MISTRAL_LOGO_25 5593.71,1401.77 r0 top
7 "Comment" MHNP_M3_PANHEAD_PHILLIPS#2 7354.16,-327.94 r180 top locked
8 "Comment" MHNP_M3_PANHEAD_PHILLIPS#2 7354.16,4992.06 r180 top
9 "Comment" MHNP_M3_PANHEAD_PHILLIPS#1 7404.17,0 r0 top locked
10 "Comment" MHNP_M3_PANHEAD_PHILLIPS#1 7404.17,2000 r0 top locked
11 "Comment" MHNP_M3_PANHEAD_PHILLIPS#2 54.16,4992.06 r0 bottom
C1 "GR442QR73D102KW01L" 1808 289.17,48.74 r180 top value=1000pF
C2 "GRM155C81C225KE11D" 0402 202.83,812.27 r90 top value=2.2uF
C3 "GRM155R71E104KE14D" 0402 291.21,1558.65 r0 top value=0.1uF
C4 "CL32B106KBJNNWE" 1210_270 344.02,345.94 r0 top value=10uF
C5 "GRM188R72A104KA35J" 0603 338.7,247.05 r0 top value=0.1uF
C6 "GRM155R71E104KE14D" 0402 330.5,1355.66 r0 top value=0.1uF
C7 "GRM155R71E104KE14D" 0402 345.31,1038.47 r0 top value=0.1uF
C8 "GRM155R71E104KE14D" 0402 318.73,1936.89 r270 top value=0.1uF
C9 "GRM155R71E104KE14D" 0402 411.06,1656.91 r90 top value=0.1uF
C10 "GRM155R71E104KE14D" 0402 427.56,812.27 r270 top value=0.1uF
C11 "GRM155R71E104KE14D" 0402 467.04,1936.89 r180 top value=0.1uF
C12 "CL32B106KBJNNWE" 1210_270 490.42,91.61 r270 top value=10uF
C13 "GRM1555C1H150JA01D" 0402 508.65,974.76 r180 top value=15pF
C14 "GRM155C71A105KE11D" FP-GRM155C71A105KE11D_0402-MFG 510,890.15 r90 top value=1µF
C15 "CL05B104KO5NNNC" 0402 614.03,301.51 r180 top value=0.1uF
C16 "GRM155R71E104KE14D" 0402 624.98,791.85 r180 top value=0.1uF
C17 "GRM155R71E104KE14D" 0402 637.63,871.22 r90 top value=0.1uF
C18 "GRM155C71A105KE11D" FP-GRM155C71A105KE11D_0402-MFG 700.81,1477.63 r90 top value=1µF
C19 "GRM155R71E104KE14D" 0402 708.51,1643.58 r90 top value=0.1uF
C20 "GRM155R71E104KE14D" 0402 711.42,1848.15 r270 top value=0.1uF
C21 "GRM155C71A105KE11D" FP-GRM155C71A105KE11D_0402-MFG 827.49,875.32 r270 top value=1µF
C22 "CL05B104KO5NNNC" 0402 921.05,359.89 r90 top value=0.1uF
C23 "GRM155C81C225KE11D" 0402 955,1071.57 r180 top value=2.2uF
C24 "GRM155R71E104KE14D" 0402 948.65,1390.91 r90 top value=0.1uF
C25 "GRM155C71A105KE11D" FP-GRM155C71A105KE11D_0402-MFG 955,1130 r0 top value=1µF
C26 "GRM155R71E104KE14D" 0402 1007.86,1856.71 r180 top value=0.1uF
C27 "CL05B104KO5NNNC" 0402 1017.44,353.62 r270 top value=0.1uF
C28 "GRM155R71E104KE14D" 0402 1105.58,709.4 r90 top value=0.1uF
C29 "GRM155R71E104KE14D" 0402 1122.11,1021.92 r90 top value=0.1uF
C30 "GRM155R71E104KE14D" 0402 1122.11,1142.48 r270 top value=0.1uF
C31 "CL32B106KBJNNWE" 1210_270 1414.33,468.16 r90 top value=10uF
C32 "GRM155R71E104KE14D" 0402 1512.87,1119.73 r180 top value=0.1uF
C33 "GRM155R71E104KE14D" 0402 1514.02,1043.59 r180 top value=0.1uF
C34 "GRM155R71E104KE14D" 0402 1489.23,706.12 r90 top value=0.1uF
C35 "CL05B104KO5NNNC" 0402 1529.67,441.28 r90 top value=0.1uF
C36 "GRM155R71E104KE14D" 0402 1604.79,1687.95 r0 top value=0.1uF
C37 "GRM155R71E104KE14D" 0402 1731.73,1469.23 r180 top value=0.1uF
C38 "GRM155R71C102KA01D" 0402 1711.37,347.77 r270 top value=1000pF
C39 "CL05B104KO5NNNC" 0402 1711.37,451.71 r90 top value=0.1uF
C40 "GRM155R71E103KA01D" 0402 1747.95,1273.35 r0 top value=0.01uF
C41 "CL32B106KBJNNWE" 1210_270 1822.38,505.1 r90 top value=10uF
C42 "GRM155R71E104KE14D" 0402 1809.5,906.48 r90 top value=0.1uF
C43 "GRM155R71E104KE14D" 0402 1921.13,1505.08 r0 top value=0.1uF
C44 "KGM05CR51A106MH" FP-KGM05CR51A106MH_0402-MFG 1986.19,464.95 r270 top value=10µF
C45 "GRM155R71H104KE14D" FP-GRM155R71H104KE14D_0402-MFG 2050.18,463.29 r90 top value=100nF
C46 "GRM155R71H104KE14D" FP-GRM155R71H104KE14D_0402-MFG 2231.35,456.71 r90 top value=100nF
C47 "GRM21BZ71E106KE15L" 0805_HV 2279.43,322.68 r270 top value=10uF
C48 "GRM155R61E225KE11D" 0402_070 2280.72,457.07 r270 top value=2.2uF
C49 "GRM155R71E104KE14D" 0402 2348.53,321.09 r90 top value=0.1uF
C50 "GRM21BZ71E106KE15L" 0805_HV 2470.62,220.9 r180 top value=10uF
C51 "GRM188R72A104KA35J" 0603 2472.11,300.99 r180 top value=0.1uF
C52 "GRM155R71E104KE14D" 0402 2497.29,851.71 r90 top value=0.1uF
C53 "GRM155R71E104KE14D" 0402 2572.78,1283.8 r270 top value=0.1uF
C54 "GRM155R71E104KE14D" 0402 2610.25,557.27 r270 top value=0.1uF
C55 "CL10A335KP8NNNC" FP-CL10A335KP8NNNC_0603-MFG 2632.78,1275.93 r90 top value=3.3µF
C56 "GRM155C71A105KE11D" FP-GRM155C71A105KE11D_0402-MFG 2665.63,558.49 r90 top value=1µF
C57 "GR442QR73D102KW01L" 1808 2808.95,223.54 r270 top value=1000pF
C58 "GCM188R71H104KA57D" 0603 2878.81,1668.67 r180 top value=0.1uF
C59 "GRM155R71E104KE14D" 0402 2886.51,1433.48 r0 top value=0.1uF
C60 "CGA4J1X7R1E475K125AC" 0805L 3131.61,368.07 r270 top value=4.7uF
C61 "GCM155C71A105KE38D" 0402_070 3181.83,364.4 r270 top value=1uF
C62 "CGA2B3X7R1H104M050BB" 0402 3222.7,261.73 r180 top value=0.1uF
C63 "CGA2B3X7R1H104M050BB" 0402 3221.59,372.88 r270 top value=0.1uF
C64 "CGA4J3X7S1A106K125AE" FP-CGA4J3X7S1A106K125AE_0805-MFG 3230.4,35.05 r270 top
C65 "GRM033Z71C104KE14D" 0201 3250.5,473.67 r270 top value=0.1uF
C66 "CGA2B3X7R1H104M050BB" 0402 3311.63,547.79 r0 top value=0.1uF
C67 "CGA4J3X7S1A106K125AE" FP-CGA4J3X7S1A106K125AE_0805-MFG 3313.72,642.08 r0 top
C68 "CGA2B3X7R1H104M050BB" 0402 3286.81,32.38 r270 top value=0.1uF
C69 "GCM155C71A105KE38D" 0402_070 3314.82,592.4 r0 top value=1uF
C70 "GCM188R71H104KA57D" 0603 3353.37,1666.87 r180 top value=0.1uF
C71 "GCM155C71A105KE38D" 0402_070 3327.91,30.55 r270 top value=1uF
C72 "GRM155R71E104KE14D" 0402 3369.75,1433.91 r0 top value=0.1uF
C73 "CGA2B3X7R1H104M050BB" 0402 3389.79,549.92 r90 top value=0.1uF
C74 "885012105010" 0402 3450.23,1338.74 r0 top value=0.1uF
C75 "GCM155C71A105KE38D" 0402_070 3456.73,536.79 r0 top value=1uF
C76 "GRM155C71A105KE11D" FP-GRM155C71A105KE11D_0402-MFG 3456.73,582.05 r0 top value=1µF
C77 "GCM155C71A105KE38D" 0402_070 3460.32,30.67 r270 top value=1uF
C78 "GRM033Z71C104KE14D" 0201 3463.78,486.52 r90 top value=0.1uF
C79 "CGA2B3X7R1H104M050BB" 0402 3508.93,418.56 r0 top value=0.1uF
C80 "CGA2B3X7R1H104M050BB" 0402 3511.36,273.17 r0 top value=0.1uF
C81 "CGA2B3X7R1H104M050BB" 0402 3513.02,321.86 r0 top value=0.1uF
C82 "CGA2B3X7R1H104M050BB" 0402 3508.11,33.1 r270 top value=0.1uF
C83 "GCM155C71A105KE38D" 0402_070 3501.76,492.82 r90 top value=1uF
C84 "CGA3E3X7S1A225K080AB" FP-CGA3E3X7S1A225K080AB_0603-MFG 3552.06,496.63 r270 top value=2.2µF
C85 "CGA4J3X7S1A106K125AE" FP-CGA4J3X7S1A106K125AE_0805-MFG 3565.66,33.1 r270 top
C86 "GRM155R71E104KE14D" 0402 3709.11,1432.89 r90 top value=0.1uF
C87 "CGA2B3X7R1H104M050BB" 0402 3799.91,700.29 r0 top value=0.1uF
C88 "GJM1555C1H120JB01D" FP-GJM1555C1H120JB01D_0402-MFG 4071.47,606.96 r90 top value=12pF
C89 "GJM1555C1H120JB01D" FP-GJM1555C1H120JB01D_0402-MFG 4072.36,676.39 r270 top value=12pF
C90 "GRM1555C1H331JA01D" 0402 4186.24,517.11 r90 top value=330pF
C91 "GRM1555C1H331JA01D" 0402 4257.17,401.37 r90 top value=330pF
C92 "GRM1555C1H331JA01D" 0402 4268.54,516.21 r90 top value=330pF
C93 "GRM1555C1H331JA01D" 0402 4340.27,401.37 r90 top value=330pF
C94 "GRM1555C1H331JA01D" 0402 4357.72,517.43 r90 top value=330pF
C95 "GRM1555C1H331JA01D" 0402 4424.28,401.37 r90 top value=330pF
C96 "GRM1555C1H331JA01D" 0402 4449.49,520.14 r90 top value=330pF
C97 "GRM1555C1H331JA01D" 0402 4507.2,401.37 r90 top value=330pF
C98 "GRM1555C1H331JA01D" 0402 4539.23,519.72 r90 top value=330pF
C99 "GRM1555C1H331JA01D" 0402 4593.17,401.37 r90 top value=330pF
C100 "GRM1555C1H331JA01D" 0402 4619.66,516.08 r90 top value=330pF
C101 "GRM1555C1H331JA01D" 0402 4694.01,401.37 r90 top value=330pF
C102 "GRM1555C1H331JA01D" 0402 4702.69,513.89 r90 top value=330pF
C103 "GRM155R71E104KE14D" 0402 4776.9,1540.34 r0 top value=0.1uF
C104 "GRM1555C1H331JA01D" 0402 4781.56,401.37 r90 top value=330pF
C105 "GRM1555C1H331JA01D" 0402 4790.1,512.83 r90 top value=330pF
C106 "GRM1555C1H331JA01D" 0402 4873.26,516.98 r90 top value=330pF
C107 "GRM155R71E104KE14D" 0402 5130.27,2014.55 r180 top value=0.1uF
C108 "GRM155R71E104KE14D" 0402 5153.78,1561.7 r270 top value=0.1uF
C109 "GRM155R71E104KE14D" 0402 5208.02,1257.86 r270 top value=0.1uF
C110 "GRM1885C1H102JA01D" 0603 5378.93,1611.36 r0 top value=1000pF
C111 "GRM188Z71A475ME15D" 0603 5417.84,256.77 r180 top value=4.7uF
C112 "GRM155R71E104KE14D" 0402 5418.4,430.75 r90 top value=0.1uF
C113 "GRM188Z71A475ME15D" 0603 5789.07,338.19 r0 top value=4.7uF
C114 "GRM155R71H472KA01D" 0402 5944.74,371.36 r90 top value=4700pF
C115 "885012105010" 0402 5959.69,945.35 r90 top value=0.1uF
C116 "GRM155R71E104KE14D" 0402 6006.75,1338.39 r180 top value=0.1uF
C117 "885012105010" 0402 6023.85,805.84 r0 top value=0.1uF
C118 "KGM05CR51A106MH" FP-KGM05CR51A106MH_0402-MFG 6023.21,861.29 r0 top value=10µF
C119 "GRM155R71E104KE14D" 0402 6057.28,254.84 r270 top value=0.1uF
C120 "885012105010" 0402 6104.06,874.55 r270 top value=0.1uF
C121 "GRM155R71E104KE14D" 0402 6357.97,1700.4 r90 top value=0.1uF
C122 "885012105010" 0402 6496.77,353.02 r270 top value=0.1uF
C123 "885012105010" 0402 6547.26,353.02 r270 top value=0.1uF
C124 "GRM155R71E104KE14D" 0402 6654.37,1445.32 r270 top value=0.1uF
C125 "885012105010" 0402 6708.05,1653.21 r90 top value=0.1uF
C126 "885012105010" 0402 6758.52,1652.4 r90 top value=0.1uF
C127 "GRM155R71E104KE14D" 0402 7190.65,559.77 r0 top value=0.1uF
C128 "GRM155R71E104KE14D" 0402 7200.3,768.73 r180 top value=0.1uF
C129 "GRM155R71E104KE14D" 0402 7263.05,380.08 r90 top value=0.1uF
C130 "GRM155R70J104KA01D" 0402 6894.24,1995.47 r0 bottom value=0.1uF
C131 "CGA4J3X7S1A106K125AE" FP-CGA4J3X7S1A106K125AE_0805-MFG 6890.5,1910.7 r0 bottom
C132 "CGA4J3X7S1A106K125AE" FP-CGA4J3X7S1A106K125AE_0805-MFG 6816.18,67.77 r270 bottom
C133 "CGA4J3X7S1A106K125AE" FP-CGA4J3X7S1A106K125AE_0805-MFG 6747.24,623.16 r90 bottom
C134 "GRM155R71E104KE14D" 0402 6750.86,68.43 r270 bottom value=0.1uF
C135 "CGA4J3X7S1A106K125AE" FP-CGA4J3X7S1A106K125AE_0805-MFG 6740.26,757.51 r270 bottom
C136 "GRM155R71E104KE14D" 0402 6689.31,643.83 r90 bottom value=0.1uF
C137 "GRM155R71E104KE14D" 0402 6686.31,743.72 r270 bottom value=0.1uF
C138 "GRM155R71E104KE14D" 0402 6502.71,1975.54 r180 bottom value=0.1uF
C139 "CGA4J3X7S1A106K125AE" FP-CGA4J3X7S1A106K125AE_0805-MFG 6495.58,1915.37 r180 bottom
C140 "CGA4J3X7S1A106K125AE" FP-CGA4J3X7S1A106K125AE_0805-MFG 6387.48,43.86 r180 bottom
C141 "GRM155R70J104KA01D" 0402 6384.06,92.98 r180 bottom value=0.1uF
C142 "GRM155R71E104KE14D" 0402 6223.11,257.71 r270 bottom value=0.1uF
C143 "885012105010" 0402 6160.51,1358.32 r180 bottom value=0.1uF
C144 "GCM188R71H104KA57D" 0603 5695.69,1599.55 r270 bottom value=0.1uF
C145 "GCM188R71H104KA57D" 0603 5695.69,1849.55 r270 bottom value=0.1uF
C146 "GRM155R71E104KE14D" 0402 5603.48,1176.44 r180 bottom value=0.1uF
C147 "GCM188R71H104KA57D" 0603 5581.9,1364.56 r0 bottom value=0.1uF
C148 "GRM1885C1H102JA01D" 0603 5575.69,1599.55 r270 bottom value=1000pF
C149 "GRM1885C1H102JA01D" 0603 5575.69,1849.55 r270 bottom value=1000pF
C150 "C0603C101J5GACTU" 0603 5451.52,1599.55 r270 bottom value=100pF
C151 "C0603C101J5GACTU" 0603 5451.52,1849.55 r270 bottom value=100pF
C152 "GRM1885C1H102JA01D" 0603 5376.52,1599.55 r270 bottom value=1000pF
C153 "GRM1885C1H102JA01D" 0603 5376.52,1849.55 r270 bottom value=1000pF
C154 "885012105010" 0402 5191.31,639.87 r270 bottom value=0.1uF
C155 "GRM1885C1H102JA01D" 0603 5178.34,1909.36 r270 bottom value=1000pF
C156 "885012105010" 0402 5139.26,1040.23 r180 bottom value=0.1uF
C157 "GRM155R71E104KE14D" 0402 5056.57,404.13 r90 bottom value=0.1uF
C158 "CL10A335KP8NNNC" FP-CL10A335KP8NNNC_0603-MFG 4891.38,873.28 r90 bottom value=3.3µF
C159 "GRM033Z71C104KE14D" 0201 4838.74,872.32 r270 bottom value=0.1uF
C160 "GRM155R71E104KE14D" 0402 4776.62,1540.83 r0 bottom value=0.1uF
C161 "CL10A335KP8NNNC" FP-CL10A335KP8NNNC_0603-MFG 4766.77,831.52 r180 bottom value=3.3µF
C162 "CL10A335KP8NNNC" FP-CL10A335KP8NNNC_0603-MFG 4766.77,969.2 r0 bottom value=3.3µF
C163 "GRM155R71E104KE14D" 0402 4729.47,1661.55 r90 bottom value=0.1uF
C164 "GRM1555C1H331JA01D" 0402 4721.73,657.61 r90 bottom value=330pF
C165 "CL10A335KP8NNNC" FP-CL10A335KP8NNNC_0603-MFG 4675.75,981.47 r90 bottom value=3.3µF
C166 "GRM033Z71C104KE14D" 0201 4650.71,545.95 r0 bottom value=0.1uF
C167 "GRM1555C1H331JA01D" 0402 4630.84,650.87 r90 bottom value=330pF
C168 "GRM188Z71A475ME15D" 0603 4532.72,814.75 r0 bottom value=4.7uF
C169 "GRM033Z71C104KE14D" 0201 4566.16,1046.19 r90 bottom value=0.1uF
C170 "GRM1555C1H331JA01D" 0402 4535.13,641.88 r90 bottom value=330pF
C171 "GRM033Z71C104KE14D" 0201 4511.73,861.53 r0 bottom value=0.1uF
C172 "GRM033Z71C104KE14D" 0201 4504.15,1051.47 r45 bottom value=0.1uF
C173 "GRM033Z71C104KE14D" 0201 4503.93,1165.06 r0 bottom value=0.1uF
C174 "GRM033Z71C104KE14D" 0201 4485.48,1106.41 r180 bottom value=0.1uF
C175 "GRM033Z71C104KE14D" 0201 4485.35,924.43 r180 bottom value=0.1uF
C176 "GRM033Z71C104KE14D" 0201 4489.53,981.92 r90 bottom value=0.1uF
C177 "GRM033Z71C104KE14D" 0201 4482.22,1202.11 r270 bottom value=0.1uF
C178 "GRM1555C1H331JA01D" 0402 4459.48,640.67 r90 bottom value=330pF
C179 "GRM033Z71C104KE14D" 0201 4443.88,1055.34 r180 bottom value=0.1uF
C180 "CL10A335KP8NNNC" FP-CL10A335KP8NNNC_0603-MFG 4434.01,790.42 r90 bottom value=3.3µF
C181 "GRM033C80J105ME05D" FP-GRM033C80J105ME05D_0201-MFG 4440.45,1111.67 r0 bottom value=1µF
C182 "GRM033C80J105ME05D" FP-GRM033C80J105ME05D_0201-MFG 4439.9,998.45 r0 bottom value=1µF
C183 "GRM033C80J105ME05D" FP-GRM033C80J105ME05D_0201-MFG 4439.44,1090.76 r0 bottom value=1µF
C184 "GRM033C80J105ME05D" FP-GRM033C80J105ME05D_0201-MFG 4438.17,965.79 r0 bottom value=1µF
C185 "GRM033C80J105ME05D" FP-GRM033C80J105ME05D_0201-MFG 4431.47,1024.12 r45 bottom value=1µF
C186 "GRM033Z71C104KE14D" 0201 4431.7,928.21 r90 bottom value=0.1uF
C187 "GRM033C80J105ME05D" FP-GRM033C80J105ME05D_0201-MFG 4429.67,1149.98 r90 bottom value=1µF
C188 "CL10A335KP8NNNC" FP-CL10A335KP8NNNC_0603-MFG 4394.89,1339.92 r0 bottom value=3.3µF
C189 "CL10A335KP8NNNC" FP-CL10A335KP8NNNC_0603-MFG 4393.92,1399.48 r0 bottom value=3.3µF
C190 "GRM033Z71C104KE14D" 0201 4400.57,1256.63 r180 bottom value=0.1uF
C191 "GRM033Z71C104KE14D" 0201 4400.12,1282.19 r180 bottom value=0.1uF
C192 "GRM033Z71C104KE14D" 0201 4386.47,1209.55 r180 bottom value=0.1uF
C193 "GRM033Z71C104KE14D" 0201 4392.4,948.12 r90 bottom value=0.1uF
C194 "GRM033C80J105ME05D" FP-GRM033C80J105ME05D_0201-MFG 4398.05,1156.44 r90 bottom value=1µF
C195 "GRM1555C1H331JA01D" 0402 4379.69,634.69 r90 bottom value=330pF
C196 "GRM033C80J105ME05D" FP-GRM033C80J105ME05D_0201-MFG 4377.67,1154.32 r90 bottom value=1µF
C197 "GRM033Z71C104KE14D" 0201 4369.18,926.82 r90 bottom value=0.1uF
C198 "GRM155R71E104KE14D" 0402 4328.29,1651.01 r180 bottom value=0.1uF
C199 "GRM033Z71C104KE14D" 0201 4347.67,554.56 r0 bottom value=0.1uF
C200 "GRM033Z71C104KE14D" 0201 4340.5,1160.87 r270 bottom value=0.1uF
C201 "GRM033Z71C104KE14D" 0201 4335.28,941.98 r90 bottom value=0.1uF
C202 "GRM188Z71A475ME15D" 0603 4285.49,652.16 r180 bottom value=4.7uF
C203 "GRM033Z71C104KE14D" 0201 4304.66,1192.22 r0 bottom value=0.1uF
C204 "GRM033Z71C104KE14D" 0201 4303.47,890.38 r180 bottom value=0.1uF
C205 "GRM033Z71C104KE14D" 0201 4289.46,701.73 r180 bottom value=0.1uF
C206 "CL10A335KP8NNNC" FP-CL10A335KP8NNNC_0603-MFG 4280.06,771.04 r90 bottom value=3.3µF
C207 "GRM033Z71C104KE14D" 0201 4279.87,918.83 r45 bottom value=0.1uF
C208 "GRM033C80J105ME05D" FP-GRM033C80J105ME05D_0201-MFG 4300.57,1155.2 r90 bottom value=1µF
C209 "GRM033Z71C104KE14D" 0201 4277.87,954.4 r0 bottom value=0.1uF
C210 "GRM033Z71C104KE14D" 0201 4277.31,849.86 r0 bottom value=0.1uF
C211 "GRM033Z71C104KE14D" 0201 4242.09,1198.57 r135 bottom value=0.1uF
C212 "GRM033C80J105ME05D" FP-GRM033C80J105ME05D_0201-MFG 4260.51,1155.01 r90 bottom value=1µF
C213 "GRM033Z71C104KE14D" 0201 4228.33,1054.3 r0 bottom value=0.1uF
C214 "GRM033Z71C104KE14D" 0201 4226.34,961.7 r0 bottom value=0.1uF
C215 "GRM033Z71C104KE14D" 0201 4222.06,1148.42 r0 bottom value=0.1uF
C216 "GRM033Z71C104KE14D" 0201 4233.88,1012.59 r90 bottom value=0.1uF
C217 "GRM033C80J105ME05D" FP-GRM033C80J105ME05D_0201-MFG 4233.38,1105.54 r180 bottom value=1µF
C218 "GRM033Z71C104KE14D" 0201 4212.05,910.86 r0 bottom value=0.1uF
C219 "GRM033Z71C104KE14D" 0201 4197.39,816.74 r180 bottom value=0.1uF
C220 "GRM033Z71C104KE14D" 0201 4197.39,842.29 r180 bottom value=0.1uF
C221 "GRM033Z71C104KE14D" 0201 4194.65,1201.42 r0 bottom value=0.1uF
C222 "GRM033Z71C104KE14D" 0201 4173.19,1159.88 r45 bottom value=0.1uF
C223 "GRM033Z71C104KE14D" 0201 4179.24,1095.75 r90 bottom value=0.1uF
C224 "GRM033Z71C104KE14D" 0201 4159.06,686.43 r180 bottom value=0.1uF
C225 "GRM033Z71C104KE14D" 0201 4171.17,1036.46 r90 bottom value=0.1uF
C226 "GRM033Z71C104KE14D" 0201 4156.26,857.93 r270 bottom value=0.1uF
C227 "GRM033Z71C104KE14D" 0201 4121.49,896.64 r270 bottom value=0.1uF
C228 "CL10A335KP8NNNC" FP-CL10A335KP8NNNC_0603-MFG 4103.27,773.89 r90 bottom value=3.3µF
C229 "GRM033C80J105ME05D" FP-GRM033C80J105ME05D_0201-MFG 4106.03,1150.34 r270 bottom value=1µF
C230 "GRM033Z71C104KE14D" 0201 4085.95,962.34 r180 bottom value=0.1uF
C231 "GRM155R71E104KE14D" 0402 4041.37,1575.01 r180 bottom value=0.1uF
C232 "CL10A335KP8NNNC" FP-CL10A335KP8NNNC_0603-MFG 4050.77,1150.62 r270 bottom value=3.3µF
C233 "GRM155R71E104KE14D" 0402 4012.93,509.32 r0 bottom value=0.1uF
C234 "CL10A335KP8NNNC" FP-CL10A335KP8NNNC_0603-MFG 3988.32,964.69 r90 bottom value=3.3µF
C235 "CL10A335KP8NNNC" FP-CL10A335KP8NNNC_0603-MFG 3979.56,1150.34 r270 bottom value=3.3µF
C236 "GRM033Z71C104KE14D" 0201 3920,982.99 r270 bottom value=0.1uF
C237 "GRM155R71E104KE14D" 0402 3761.86,248.08 r0 bottom value=0.1uF
C238 "GRM155R71E104KE14D" 0402 3759.47,542.75 r180 bottom value=0.1uF
C239 "GCM188R71H104KA57D" 0603 3718.88,1851.94 r270 bottom value=0.1uF
C240 "CL10A335KP8NNNC" FP-CL10A335KP8NNNC_0603-MFG 3655.94,1066.5 r90 bottom value=3.3µF
C241 "CL10A335KP8NNNC" FP-CL10A335KP8NNNC_0603-MFG 3600.18,542.74 r270 bottom value=3.3µF
C242 "CGA4J3X7S1A106K125AE" FP-CGA4J3X7S1A106K125AE_0805-MFG 3505.64,280.85 r0 bottom
C243 "CGA3E3X7S1A225K080AB" FP-CGA3E3X7S1A225K080AB_0603-MFG 3523.11,451.02 r270 bottom value=2.2µF
C244 "GCM155C71A105KE38D" 0402_070 3508.09,329.52 r0 bottom value=1uF
C245 "GCM155C71A105KE38D" 0402_070 3473.79,447.26 r90 bottom value=1uF
C246 "885012105010" 0402 3383.78,1008.52 r0 bottom value=0.1uF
